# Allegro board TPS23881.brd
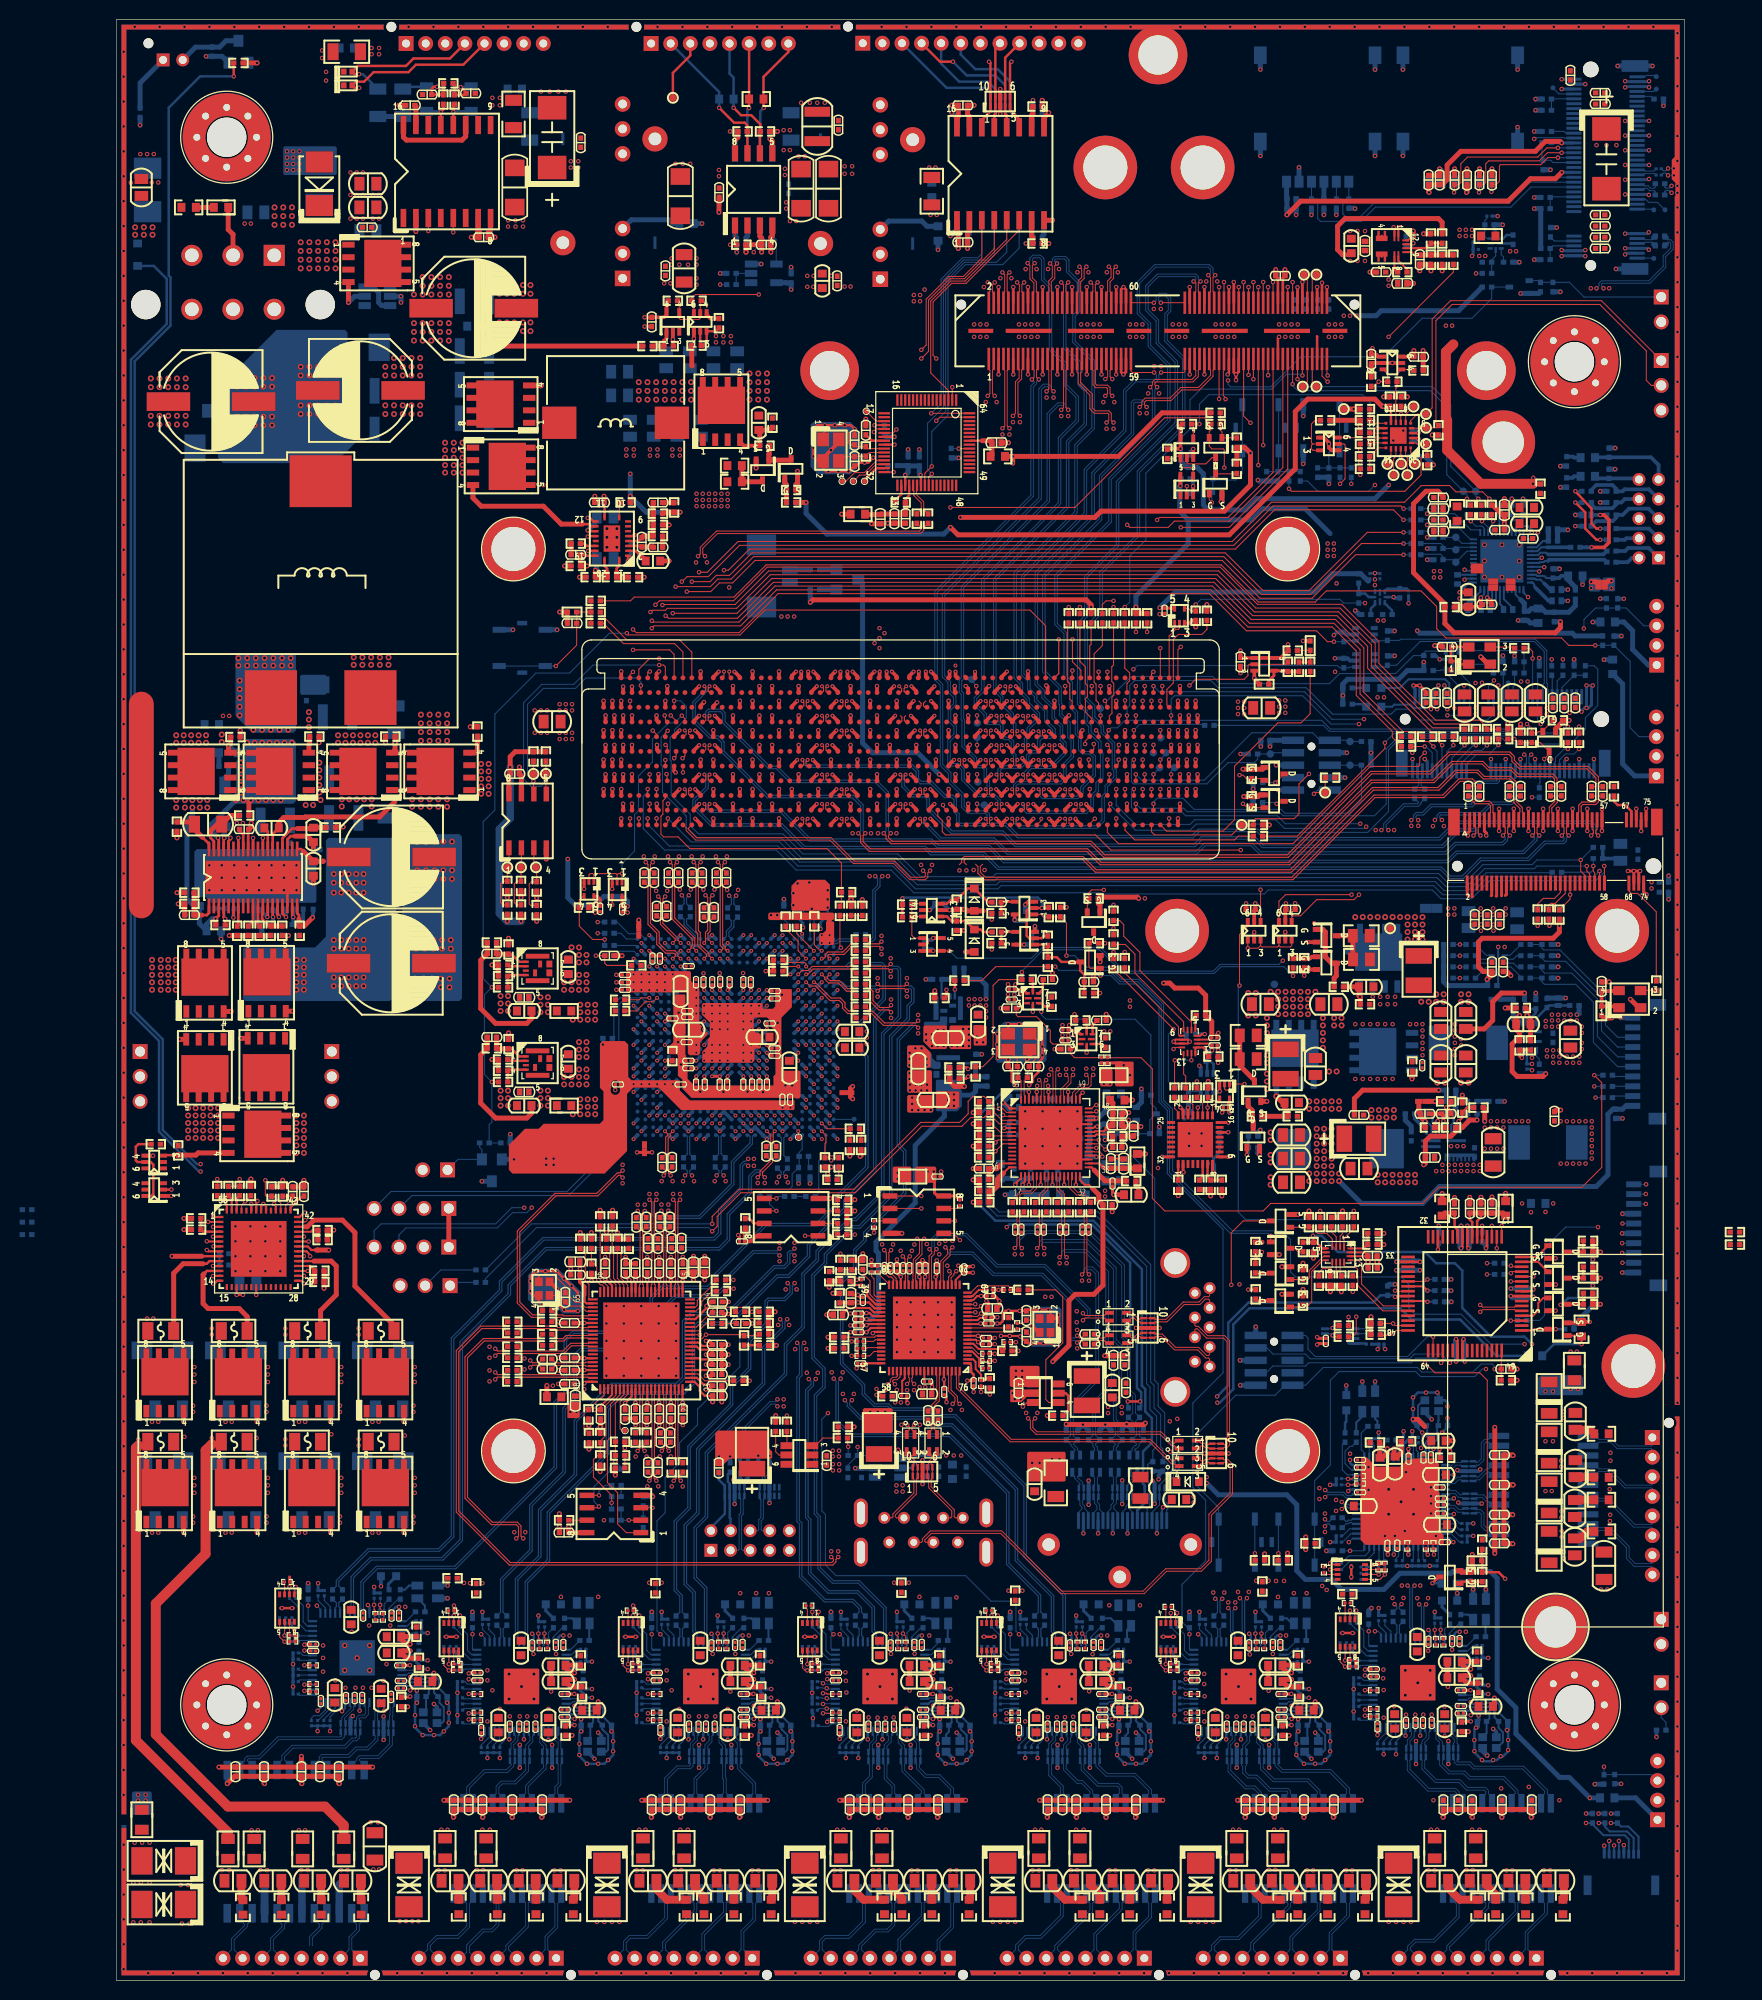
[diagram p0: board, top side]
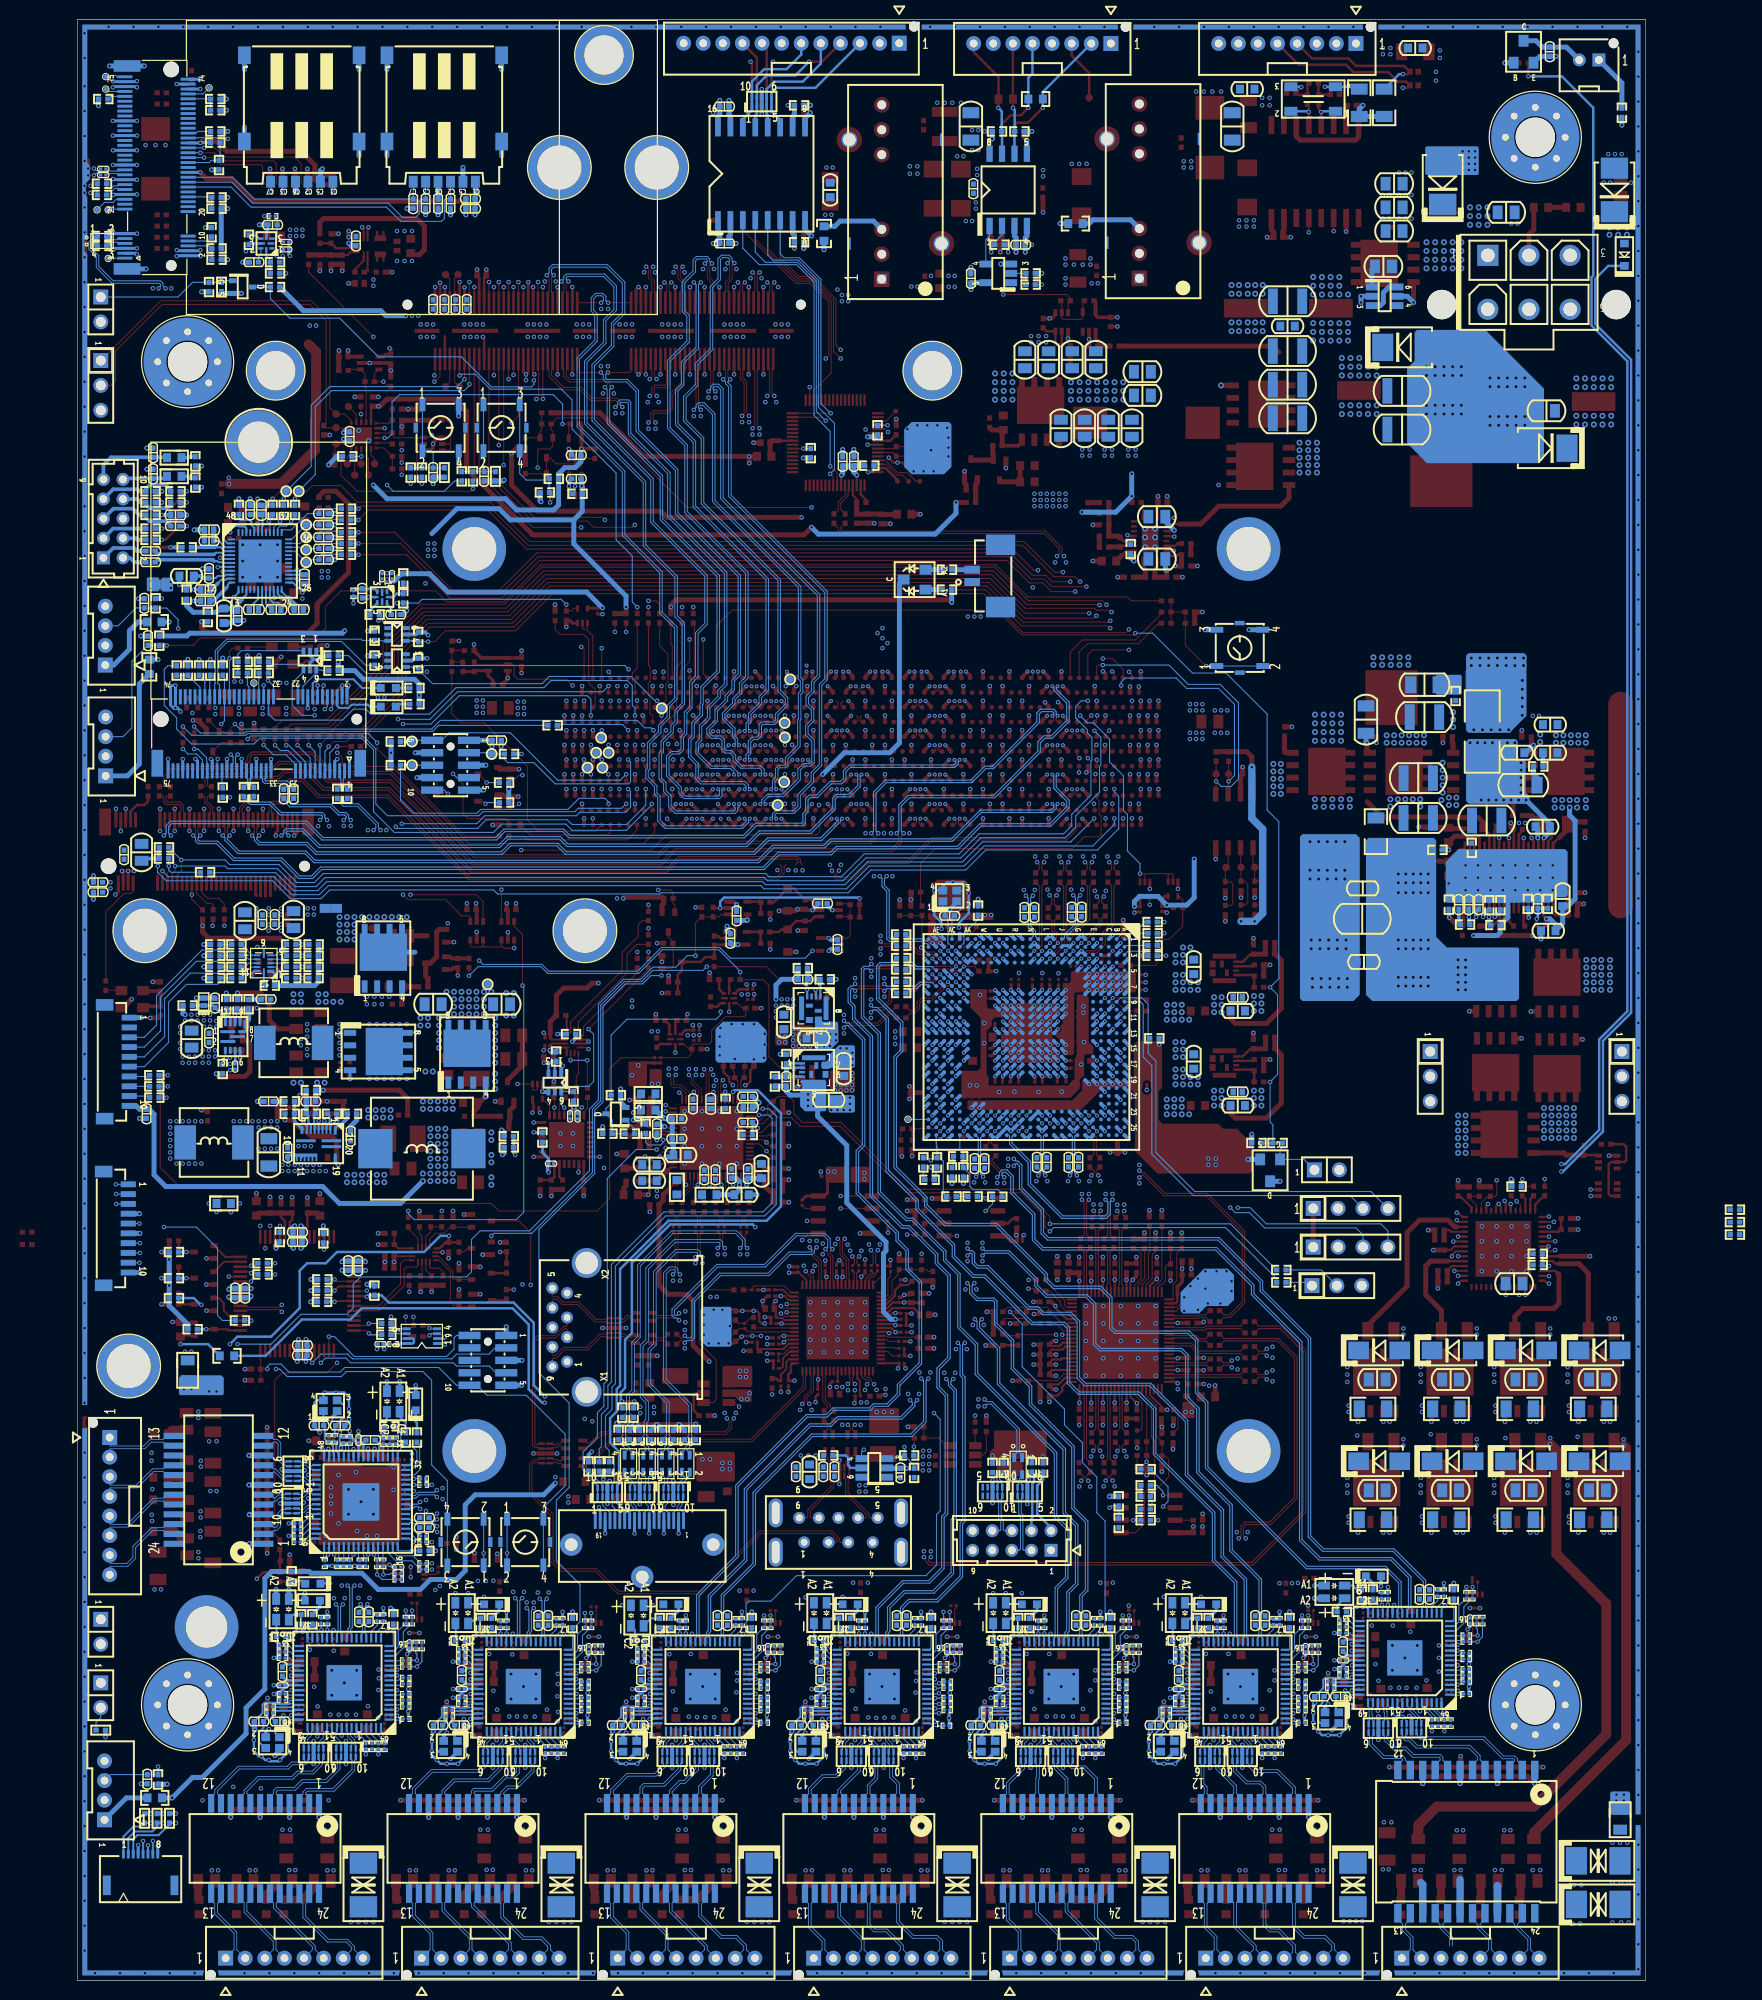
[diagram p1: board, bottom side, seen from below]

Outline 160 x 200 mm; copper layers: TOP, GND1, IN1, IN2, VCC, IN3, GND2, BOTTOM. Coordinates in mm from the lower left corner of the outline.
Outline path: 0,200 160,200 160,0 0,0 0,200

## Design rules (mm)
constraint set DEFAULT: min track width 0.107
net group 422RX: nets 422RX+ 422RX-
net group AUDIO_CP1: nets AUDIO_CPN1 AUDIO_CPP1
net group AUDIO_CP2: nets AUDIO_CPN2 AUDIO_CPP2
net group CAM_TE_RSV: nets CAM_TE_RSV N16109
net group N17978352: nets N17978352 N17978356
net group N17978410: nets N17978406 N17978410
net group N17979269: nets N17979269 N17979281
net group N17981424: nets N17981424 N17981427
net group N17981727: nets N17981727 N17981744
net group N17982049: nets N17982049 N17982065
net group N17982135: nets N17982119 N17982135
net group N17983399: nets N17983399 N17983402
net group N17983405: nets N17983405 N17983408
net group N17983600: nets N17983588 N17983600
net group N17983616: nets N17983612 N17983616
net group N17983708: nets N17983696 N17983708
net group N17983724: nets N17983720 N17983724
net group N17983816: nets N17983804 N17983816
net group N17983832: nets N17983828 N17983832
net group N17985522: nets N17985522 N17985526
net group N17985638: nets N17985638 N17985642
net group N17985774: nets N17985774 N17985778
net group N17985910: nets N17985910 N17985914
net group N17986046: nets N17986046 N17986050
net group N17986184: nets N17986184 N17986188
net group N17986320: nets N17986320 N17986324
net group N17986454: nets N17986454 N17986458
net group N18237080: nets N18237049 N18237080
net group N18237422: nets N18237399 N18237422
net group N18237490: nets N18237476 N18237490
net group N54184803: nets N54184803 N54186028
net group N54465893: nets N54465881 N54465893
net group SBU2: nets SBU1 SBU2
net group TYPEC0_DP-E: nets TYPEC0_DM-E TYPEC0_DP-E
net group USB2_1N_CON: nets USB2_1N_CON USB2_1P_CON
net group USB2_2N_CON: nets USB2_2N_CON USB2_2P_CON
net group USB2_DWN_DM1: nets USB2_DWN_DM1 USB2_DWN_DP1
net group USB2_DWN_DM2: nets USB2_DWN_DM2 USB2_DWN_DP2
net group USB2_DWN_DM3: nets USB2_DWN_DM3 USB2_DWN_DP3
net group USB2_DWN_DP4: nets USB2_DWN_DM4 USB2_DWN_DP4
net group USB3_RXN1_CON: nets USB3_RXN1_CON USB3_RXP1_CON
net group USB3_RXP2_CON: nets USB3_RXN2_CON USB3_RXP2_CON
net group USB3_TXN1_CON: nets USB3_TXN1_CON USB3_TXP1_CON
net group USB3_TXP2_CON: nets USB3_TXN2_CON USB3_TXP2_CON
net group AC97-50OHM: nets I2S1_DIN I2S1_DIN_CDC I2S1_DOUT I2S1_DOUT_CDC I2S1_FS I2S1_FS_CDC I2S1_SCLK I2S1_SCLK_CDC
net group CLK-85OHM: nets 12DPE_CLKN0 12DPE_CLKP0 DPE_CLKN0 DPE_CLKN1 DPE_CLKN2 DPE_CLKP0 DPE_CLKP1 DPE_CLKP2 LAN_CLKN1 LAN_CLKN2 LAN_CLKN3 LAN_CLKN4 LAN_CLKN5 LAN_CLKN6 LAN_CLKN7 LAN_CLKN8 LAN_CLKP1 LAN_CLKP2 LAN_CLKP3 LAN_CLKP4 LAN_CLKP5 LAN_CLKP6 LAN_CLKP7 LAN_CLKP8 N54369784 N54371660 PCIE4_CLK_N PCIE4_CLK_P PCIE5_CLK_N PCIE5_CLK_P UPE_CLKN UPE_CLKP UPHY0_SF_PCIE1_CLK_N UPHY0_SF_PCIE1_CLK_P
net group CLK-OTHER-50OHM: nets 06UPE_CLKREQN 12DPE_CLKREQN0 12DPE_CLKREQN1 12DPE_CLKREQN2 12DPE_CLKREQN3 12DPE_CLKREQN4 12DPE_CLKREQN5 AUD_MCLK01_CDC CLK-ISP0 CLK-ISP0# CLKREQ_M2_KEY_B_N DPE_CLKREQN0 DPE_CLKREQN1 DPE_CLKREQN2 DPE_CLKREQN3 M.2_WIFI_SUS_CLK MCLK01_AUDIO_MCLK MCLK02_CAM0_MCLK MCLK02_MCLK MCLK03_CAM1_MCLK MCLK03_MCLK MCLK04_CAM2_MCLK MCLK04_MCLK NC_SI1_CLK NCSI4_CLKIN P0_TOD_CLK_IN_3V3 P1_TOD_CLK_IN_3V3 PCIE1_CLKREQ_N PCIE4_CLKREQ_N PCIE5_CLKREQ_N SW2CLK UFS0_REF_CLK UPE_CLKREQN
net group CSI-90OHM: nets CSI_0_CLK_N CSI_0_CLK_P CSI_0_D0_N CSI_0_D0_P CSI_0_D1_N CSI_0_D1_P CSI_1_CLK_N CSI_1_CLK_P CSI_1_D0_N CSI_1_D0_P CSI_1_D1_N CSI_1_D1_P CSI_2_CLK_N CSI_2_CLK_P CSI_2_D0_N CSI_2_D0_P CSI_2_D1_N CSI_2_D1_P CSI_3_CLK_N CSI_3_CLK_P CSI_3_D0_N CSI_3_D0_P CSI_3_D1_N CSI_3_D1_P CSI_4_CLK_N CSI_4_CLK_P CSI_4_D0_N CSI_4_D0_P CSI_4_D1_N CSI_4_D1_P CSI_5_CLK_N CSI_5_CLK_P CSI_5_D0_N CSI_5_D0_P CSI_5_D1_N CSI_5_D1_P CSI_6_CLK_N CSI_6_CLK_P CSI_6_D0_N CSI_6_D0_P CSI_6_D1_N CSI_6_D1_P CSI_7_CLK_N CSI_7_CLK_P CSI_7_D0_N CSI_7_D0_P CSI_7_D1_N CSI_7_D1_P
net group EMMC-50OHM: nets N18237134 N18237158 N18237182 N18237217 N18237240 N18237264 SDMMC1_CLK SDMMC1_CMD SDMMC1_D0 SDMMC1_D1 SDMMC1_D2 SDMMC1_D3
net group HDMI-100OHM: nets E_TX0N_A E_TX0N_R_A E_TX0P_A E_TX0P_R_A E_TX1N_A E_TX1N_R_A E_TX1P_A E_TX1P_R_A E_TX2N_A E_TX2N_R_A E_TX2P_A E_TX2P_R_A E_TXCN_A E_TXCN_R_A E_TXCP_A E_TXCP_R_A HDMI_DP0_TX0_N HDMI_DP0_TX0_P HDMI_DP0_TX1_N HDMI_DP0_TX1_P HDMI_DP0_TX2_N HDMI_DP0_TX2_P HDMI_DP0_TX3_N HDMI_DP0_TX3_P TX0N_A TX0N_A-E TX0P_A TX0P_A-E TX1N_A TX1N_A-E TX1P_A TX1P_A-E TX2N_A TX2N_A-E TX2P_A TX2P_A-E TXCN_A TXCN_A-E TXCP_A TXCP_A-E
net group LAN-100OHM: nets LAN1_MDI0+ LAN1_MDI0+_T LAN1_MDI0- LAN1_MDI0-_T LAN1_MDI1+ LAN1_MDI1+_T LAN1_MDI1- LAN1_MDI1-_T LAN1_MDI2+ LAN1_MDI2+_T LAN1_MDI2- LAN1_MDI2-_T LAN1_MDI3+ LAN1_MDI3+_T LAN1_MDI3- LAN1_MDI3-_T LAN2_MDI0+ LAN2_MDI0+_T LAN2_MDI0- LAN2_MDI0-_T LAN2_MDI1+ LAN2_MDI1+_T LAN2_MDI1- LAN2_MDI1-_T LAN2_MDI2+ LAN2_MDI2+_T LAN2_MDI2- LAN2_MDI2-_T LAN2_MDI3+ LAN2_MDI3+_T LAN2_MDI3- LAN2_MDI3-_T LAN3_MDI0+ LAN3_MDI0+_T LAN3_MDI0- LAN3_MDI0-_T LAN3_MDI1+ LAN3_MDI1+_T LAN3_MDI1- LAN3_MDI1-_T LAN3_MDI2+ LAN3_MDI2+_T LAN3_MDI2- LAN3_MDI2-_T LAN3_MDI3+ LAN3_MDI3+_T LAN3_MDI3- LAN3_MDI3-_T LAN4_MDI0+ LAN4_MDI0+_T LAN4_MDI0- LAN4_MDI0-_T LAN4_MDI1+ LAN4_MDI1+_T LAN4_MDI1- LAN4_MDI1-_T LAN4_MDI2+ LAN4_MDI2+_T LAN4_MDI2- LAN4_MDI2-_T LAN4_MDI3+ LAN4_MDI3+_T LAN4_MDI3- LAN4_MDI3-_T LAN5_MDI0+ LAN5_MDI0+_T LAN5_MDI0- LAN5_MDI0-_T LAN5_MDI1+ LAN5_MDI1+_T LAN5_MDI1- LAN5_MDI1-_T LAN5_MDI2+ LAN5_MDI2+_T LAN5_MDI2- LAN5_MDI2-_T LAN5_MDI3+ LAN5_MDI3+_T LAN5_MDI3- LAN5_MDI3-_T LAN6_MDI0+ LAN6_MDI0+_T LAN6_MDI0- LAN6_MDI0-_T LAN6_MDI1+ LAN6_MDI1+_T LAN6_MDI1- LAN6_MDI1-_T LAN6_MDI2+ LAN6_MDI2+_T LAN6_MDI2- LAN6_MDI2-_T LAN6_MDI3+ LAN6_MDI3+_T LAN6_MDI3- LAN6_MDI3-_T LAN7_MDI0+ LAN7_MDI0+_T LAN7_MDI0- LAN7_MDI0-_T LAN7_MDI1+ LAN7_MDI1+_T LAN7_MDI1- LAN7_MDI1-_T LAN7_MDI2+ LAN7_MDI2+_T LAN7_MDI2- LAN7_MDI2-_T LAN7_MDI3+ LAN7_MDI3+_T LAN7_MDI3- LAN7_MDI3-_T LAN8_MDI0+ LAN8_MDI0+_T LAN8_MDI0- LAN8_MDI0-_T LAN8_MDI1+ LAN8_MDI1+_T LAN8_MDI1- LAN8_MDI1-_T LAN8_MDI2+ LAN8_MDI2+_T LAN8_MDI2- LAN8_MDI2-_T LAN8_MDI3+ LAN8_MDI3+_T LAN8_MDI3- LAN8_MDI3-_T
net group NCSI-50OHM: nets NCSI4_ARBIN NCSI4_ARBOUT NCSI4_CRS_DV NCSI4_RXD0 NCSI4_RXD1 NCSI4_TX_EN NCSI4_TXD0 NCSI4_TXD1
net group PCIE4-85OHM: nets UPHY0_RX4_N UPHY0_RX4_P UPHY0_RX5_N UPHY0_RX5_P UPHY0_TX4_N UPHY0_TX4_N_M2M UPHY0_TX4_P UPHY0_TX4_P_M2M UPHY0_TX5_N UPHY0_TX5_N_M2M UPHY0_TX5_P UPHY0_TX5_P_M2M UPHY0_TX6_N_M2M UPHY0_TX6_P_M2M UPHY0_TX7_N_M2M UPHY0_TX7_P_M2M UPHY_RX10_N UPHY_RX10_P UPHY_RX11_N UPHY_RX11_P UPHY_TX10_N UPHY_TX10_P UPHY_TX11_N UPHY_TX11_P
net group PCIE-85OHM: nets 12DPE_RXN0 12DPE_RXN1 12DPE_RXP0 12DPE_RXP1 12DPE_TXN0 12DPE_TXN1 12DPE_TXP0 12DPE_TXP1 DPE_RXN0 DPE_RXN1 DPE_RXN6 DPE_RXP0 DPE_RXP1 DPE_RXP6 DPE_TXN0 DPE_TXN1 DPE_TXN6 DPE_TXP0 DPE_TXP1 DPE_TXP6 N17979323 N17979335 N17979425 N17979437 PCIE_RXN1 PCIE_RXN2 PCIE_RXN3 PCIE_RXN4 PCIE_RXN5 PCIE_RXN6 PCIE_RXN7 PCIE_RXN8 PCIE_RXP1 PCIE_RXP2 PCIE_RXP3 PCIE_RXP4 PCIE_RXP5 PCIE_RXP6 PCIE_RXP7 PCIE_RXP8 PCIE_TXN1 PCIE_TXN2 PCIE_TXN3 PCIE_TXN4 PCIE_TXN5 PCIE_TXN6 PCIE_TXN7 PCIE_TXN8 PCIE_TXP1 PCIE_TXP2 PCIE_TXP3 PCIE_TXP4 PCIE_TXP5 PCIE_TXP6 PCIE_TXP7 PCIE_TXP8 RXPE_UP TXNE_UP TXPE_UP UPE_RXN0 UPE_RXN1 UPE_RXP0 UPE_RXP1 UPE_TXN0 UPE_TXN1 UPE_TXP0 UPE_TXP1 UPHY0_RX2_N UPHY0_RX2_P UPHY0_RX3_N UPHY0_RX3_P UPHY0_TX2_N UPHY0_TX2_P UPHY0_TX3_N UPHY0_TX3_P UPHY1_RX0_N UPHY1_RX0_P UPHY1_RX1_N UPHY1_RX1_P UPHY1_RX2_N UPHY1_RX2_P UPHY1_RX3_N UPHY1_RX3_P UPHY1_TX0_N UPHY1_TX0_P UPHY1_TX1_N UPHY1_TX1_P UPHY1_TX2_N UPHY1_TX2_P UPHY1_TX3_N UPHY1_TX3_P UPHY_RX0_N UPHY_RX0_P UPHY_TX0_N UPHY_TX0_P
net group POWER: nets ISO_+V12S
net group RST-50OHM: nets 06DPE_RSTN 06DPE_RSTN_R 06PERSTN 12DPE_RSTN 1812_RST_N CAM0_RST CAM1_RST DPE_RSTN_R EFM8_RST_MON JTAG_TRST_N M2_5G_PLTRST_N M2_WIFI_PLTRST_N MCU2_RST# PCIE1_RST_N PCIE4_RST_N PCIE5_RST_N PCIE5_RST_N1 PCIE5RST_N PCIE_RST# PLTRST#_TPM POE_RST# SYS_RST_IN_N SYS_RST_IN_N_CON SYS_RST_IN_N_KEY SYS_RST_IN_Q SYSRST#_OOB UFS0_RST_N USBHUB_PLTRST_N
net group RXNE_UP: nets RXNE_UP
net group SMB-50OHM: nets DIO_SCL DIO_SDA DP2_AUX_CH_N_I2C6_DAT DP2_AUX_CH_P_I2C6_CLK EFM8SB10_C2CK EFM8SB10_C2D HMCU_SCL_A HMCU_SDA_A I2C_GP1_CLK I2C_GP1_DAT I2C_GP2_CLK I2C_GP2_CLK_3V3 I2C_GP2_DAT I2C_GP2_DAT_3V3 I2C_GP3_CLK I2C_GP3_DAT I2C_GP9_CLK I2C_GP9_DAT I2C_SCL_CDC I2C_SDA_CDC I2S4_DIN I2S4_DOUT I2S4_FS I2S4_SCLK MCU_SCL_A MCU_SDA_A POE_SCL POE_SDA SPI1_MOSI TX_SCL_A TX_SDA_A
net group SPI-50OHM: nets 3V3_SPI_CLK 3V3_SPI_MISO_IO1 3V3_SPI_MOSI_IO0 06SPI_CS 06SPI_SCK 06SPI_SDIO 06SPI_SDIO1 1812SPI_CS 1812SPI_SCK 1812SPI_SCK_P 1812SPI_SDIO 1812SPI_SDIO1 1812SPI_SDIO_P CAM_SPI_CS0 CAM_SPI_MISO CAM_SPI_MOSI CAM_SPI_SCK P_SPI_CK P_SPI_CZ P_SPI_DI P_SPI_DO P_SPI_HOLD# P_SPI_WP# SPI1_CS0 SPI1_MISO SPI1_SCK TPM_SPI_CS0 TPM_SPI_MISO TPM_SPI_MOSI TPM_SPI_SCK
net group UART-50OHM: nets 06UART_RX 06UART_TX 1812UART_TX 1812UART_TX_P UART0_RX_OOB_3V3 UART0_TX_OOB_3V3 UART1_CTS UART1_RTS UART1_RXD UART1_TXD UART2_CTS UART2_RTS UART2_RX_OOB_3V3 UART2_RXD UART2_RXD_3V3 UART2_TX_OOB_3V3 UART2_TXD UART2_TXD_3V3 UART3_RXD UART3_TXD UART5_CTS UART5_RTS UART5_RXD UART5_TXD UART1812_RX UART1812_TX UART_RXD UART_TXD
net group UIM-50OHM: nets UIM1_CLK UIM1_DATA UIM1_DET UIM1_RESET UIM2_CLK UIM2_DATA UIM2_DET UIM2_RESET
net group USB-90OHM: nets DM DP N60625316 N60625341 N63438290 N63438309 USB2_0_N USB2_0_P USB2_1_N USB2_1_P USB2_2_N USB2_2_P USB2_3_N USB2_3_P USB3_DWN_RXN1 USB3_DWN_RXN2 USB3_DWN_RXP1 USB3_DWN_RXP2 USB3_DWN_TXN1 USB3_DWN_TXN2 USB3_DWN_TXP1 USB3_DWN_TXP2 USB31_RX_DN USB31_RX_DP USB31_TX_DN USB31_TX_DP USB_N0 USB_P0

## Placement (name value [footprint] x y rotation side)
AUDIO1  WF200-10/CI0110P1VD0-NH  [WF200D-5X2P-CI01]  156.34 149.1 270 bottom
AUTOPW1  PH254-2X1  [CONHD2X1]  157.61 30.35 270 bottom
BAT1  WF125-2/85205-02  [WF125S-2P-85205]  68.71 143.26 90 bottom
BUZZ1  WF200-2/B02B-PASK(LF)(SN)  [WF200D-2P-PASK]  4.76 195.89 180 bottom
C1  22U/25V/X5R-C5  [SM0805_C]  116.84 129.79 0 top
C2  22U/25V/X5R-C5  [SM0805_C]  44.45 128.4 180 top
C10  1U/10V/X7R-C2  [SM0402_C]  89.81 106.93 180 top
C18  0.01U/50V/X7R-C2  [SM0402_C]  137.54 76.33 180 bottom
C19  0.01U/50V/X7R-C2  [SM0402_C]  137.03 64.77 180 bottom
C20  0.01U/50V/X7R-C2  [SM0402_C]  131.34 72.9 270 bottom
C21  0.01U/50V/X7R-C2  [SM0402_C]  132.36 72.9 270 bottom
C22  0.01U/50V/X7R-C2  [SM0402_C]  140.34 78.74 90 top
C23  1U/10V/X5R-C2  [SM0402_C]  139.22 78.74 90 top
C24  1U/10V/X5R-C2  [SM0402_C]  141.76 62.36 0 top
C25  1U/10V/X5R-C2  [SM0402_C]  136.53 78.74 90 top
C27  2.2U/25V/X5R-C2  [SM0402_CM]  141.22 149.99 90 bottom
C30  2.2U/25V/X5R-C2  [SM0402_CM]  141.6 149.99 90 top
C34  10U/10V/X5R-C3  [SM0603_C]  143.89 148.59 180 top
C35  10U/10V/X5R-C3  [SM0603_C]  143.89 150.24 180 top
C38  10U/10V/X5R-C3  [SM0603_C]  145.03 139.19 270 bottom
C40  2.2U/25V/X5R-C2  [SM0402_CM]  146.56 147.96 0 bottom
C42  10U/10V/X5R-C3  [SM0603_C]  137.92 140.84 90 top
C43  2.2U/25V/X5R-C2  [SM0402_CM]  139.7 139.83 180 bottom
C44  1U/16V/X5R-C2  [SM0402_C]  149.99 148.34 180 bottom
C45  2.2U/25V/X5R-C2  [SM0402_CM]  141.99 139.83 0 bottom
C46  2.2U/25V/X5R-C2  [SM0402_CM]  137.41 139.83 180 bottom
C47  2.2U/25V/X5R-C2  [SM0402_CM]  136.83 142.9 270 bottom
C54  10U/10V/X5R-C3  [SM0603_C]  148.84 143.26 0 bottom
C57  12P-C2  [SM0402_C]  92.84 67.82 90 top
C58  12P-C2  [SM0402_C]  92.84 65.66 270 top
C59  10U/6.3V/X5R-C2  [SM0402_CM]  74.93 69.6 90 top
C60  @1U/50V/X5R-C2  [SM0402_C]  76.15 72.97 90 top
C61  10U/6.3V/X5R-C2  [SM0402_CM]  82.7 59.82 0 top
C62  10U/6.3V/X5R-C2  [SM0402_CM]  73.61 67.89 180 top
C63  1U/16V/X5R-C2  [SM0402_C]  92.02 60.4 270 top
C64  1U/16V/X5R-C2  [SM0402_C]  76.02 51.77 90 bottom
C65  22U/10V/X5R-C3  [SM0603_C]  101.6 60.2 270 top
C66  470P-C2  [SM0402_C]  101.73 63.25 90 top
C67  22U/10V/X5R-C3  [SM0603_C]  85.29 51.88 90 bottom
C68  470P-C2  [SM0402_C]  83.9 51.89 90 bottom
C69  1U/10V/X5R-C2  [SM0402_C]  79.38 149.1 90 top
C70  1U/10V/X5R-C2  [SM0402_C]  76.45 158.12 90 top
C71  10U/6.3V/X5R-C2  [SM0402_CM]  77.93 149.05 90 top
C72  10P-C2  [SM0402_C]  75.31 154.94 270 top
C73  10P-C2  [SM0402_C]  75.31 157.1 90 top
C74  1000P/3KV-C8  [SM1808_C]  72.64 182.75 90 top
C75  4.7U/16V/X5R-C3  [SM0603_C]  72.01 173.35 270 top
C76  10U/50V/X7R-C10  [SM1210_C]  71.5 189.1 270 top
C77  4.7U/50V/X7R-C6  [SM1206_C]  68.83 189.1 90 bottom
C78  1000P/3KV-C8  [SM1808_C]  69.85 182.75 90 top
C79  1000P-C3  [SM0603_C]  83.19 182.63 90 bottom
C80  1U/16V/X5R-C2  [SM0402_C]  72.47 53.04 90 top
C81  10U/10V/X5R-C5  [SM0805_C]  137.54 130.3 270 top
C82  0.01U/50V/X7R-C2  [SM0402_C]  134.62 130.81 270 top
C83  @10U/10V/X5R-C5  [SM0805_C]  139.95 130.3 270 top
C84  0.01U/50V/X7R-C2  [SM0402_C]  133.6 130.81 270 top
C87  0.01U/50V/X7R-C2  [SM0402_C]  147.7 130.3 270 top
C88  10U/10V/X5R-C5  [SM0805_C]  144.78 130.3 270 top
C89  0.01U/50V/X7R-C2  [SM0402_C]  148.84 130.3 270 top
C90  @10U/10V/X5R-C5  [SM0805_C]  142.37 130.3 270 top
C91  1U/6.3V/X5R-C1  [SM0201_C]  128.91 143.23 90 bottom
C92  1000P-C2  [SM0402_C]  127.51 139.32 180 bottom
C110  4.7P-C2  [SM0402_C]  151.38 192.53 0 top
C111  6.8P-C2  [SM0402_C]  151.38 180.09 180 top
C112  8.2P-C2  [SM0402_C]  148.34 194.31 270 top
C113  10P-C2  [SM0402_C]  151.38 191.39 180 top
C117  33P-C2  [SM0402_C]  123.19 181.23 90 bottom
C118  33P-C2  [SM0402_C]  125.73 181.23 90 bottom
C119  33P-C2  [SM0402_C]  119.89 180.72 180 bottom
C120  33P-C2  [SM0402_C]  124.46 181.23 90 bottom
C121  33P-C2  [SM0402_C]  121.92 181.23 90 bottom
C123  33P-C2  [SM0402_C]  137.79 183.64 270 top
C124  33P-C2  [SM0402_C]  140.34 183.64 270 top
C125  33P-C2  [SM0402_C]  139.06 183.64 270 top
C126  33P-C2  [SM0402_C]  136.53 183.64 270 top
C128  33P-C2  [SM0402_C]  135 183.64 270 top
C129  1U/6.3V/X5R-C1  [SM0201_C]  138.68 176.56 180 bottom
C130  1000P-C2  [SM0402_C]  141.99 175.26 0 bottom
C132  1000P-C2  [SM0402_C]  118.49 153.42 270 bottom
C134  1000P-C2  [SM0402_C]  123.7 153.8 270 bottom
C135  1000P-C2  [SM0402_C]  46.48 138.43 180 top
C136  0.47U/50V/X5R-C2  [SM0402_C]  118.75 173.86 180 top
C137  0.47U/50V/X5R-C2  [SM0402_C]  123.7 170.94 270 bottom
C138  0.47U/50V/X5R-C2  [SM0402_C]  120.27 170.94 270 bottom
C139  0.47U/50V/X5R-C2  [SM0402_C]  121.41 170.94 270 bottom
C140  0.47U/50V/X5R-C2  [SM0402_C]  122.56 170.94 270 bottom
C141  10U/10V/X5R-C2  [SM0402_CM]  131.19 173.1 0 top
C142  10U/10V/X5R-C2  [SM0402_CM]  127.38 176.91 90 top
C143  47U/6.3V/X5R-C3  [SM0603_C]  125.98 176.91 90 top
C155  1000P/3KV-C8  [SM1808_C]  57.53 181.99 90 top
C156  4.7U/50V/X7R-C6  [SM1206_C]  57.91 174.62 270 top
C157  4.7U/50V/X7R-C6  [SM1206_C]  42.16 189.1 90 bottom
C158  1000P/3KV-C8  [SM1808_C]  40.64 182.88 90 top
C159  1000P-C3  [SM0603_C]  40.64 192.91 0 bottom
C160  1000P-C3  [SM0603_C]  23.5 197.1 0 bottom
C162  68P/100V/NPO-C2  [SM0402_C]  31.7 192.35 180 top
C163  4700P-C2  [SM0402_C]  29.97 191.26 0 top
C164  68P/100V/NPO-C2  [SM0402_C]  36.14 192.48 0 top
C166  10U/6.3V/X5R-C3  [SM0603_C]  28.32 35.05 180 top
C167  10U/6.3V/X5R-C3  [SM0603_C]  28.32 33.4 180 top
C168  22U/6.3V/X5R-C3  [SM0603_C]  23.95 37.06 270 top
C169  10U/6.3V/X5R-C3  [SM0603_C]  27 29.01 90 top
C170  10U/6.3V/X5R-C3  [SM0603_C]  31.5 30.48 0 top
C171  0.039U/16V/X7R-C2  [SM0402_C]  30.86 34.04 90 bottom
C172  10U/6.3V/X5R-C3  [SM0603_C]  22.28 29.08 90 top
C173  27P-C2  [SM0402_C]  33.27 28.96 0 bottom
C174  27P-C2  [SM0402_C]  31.11 28.96 180 bottom
C175  10U/6.3V/X5R-C3  [SM0603_C]  45.09 32.13 180 top
C176  10U/6.3V/X5R-C3  [SM0603_C]  45.09 30.48 180 top
C177  22U/6.3V/X5R-C3  [SM0603_C]  41.27 33.91 270 top
C178  10U/6.3V/X5R-C3  [SM0603_C]  44.07 26.04 90 top
C179  10U/6.3V/X5R-C3  [SM0603_C]  48.26 27.56 0 top
C180  0.039U/16V/X7R-C2  [SM0402_C]  47.62 31.11 90 bottom
C181  10U/6.3V/X5R-C3  [SM0603_C]  38.96 26.04 90 top
C182  27P-C2  [SM0402_C]  50.04 26.04 0 bottom
C183  27P-C2  [SM0402_C]  47.88 26.04 180 bottom
C184  10U/6.3V/X5R-C3  [SM0603_C]  63.37 32.13 180 top
C185  10U/6.3V/X5R-C3  [SM0603_C]  63.37 30.48 180 top
C186  22U/6.3V/X5R-C3  [SM0603_C]  59.56 33.91 270 top
C187  10U/6.3V/X5R-C3  [SM0603_C]  62.36 26.04 90 top
C188  10U/6.3V/X5R-C3  [SM0603_C]  66.55 27.56 0 top
C189  0.039U/16V/X7R-C2  [SM0402_C]  65.91 31.11 90 bottom
C190  10U/6.3V/X5R-C3  [SM0603_C]  57.25 26.04 90 top
C191  27P-C2  [SM0402_C]  68.33 26.04 0 bottom
C192  27P-C2  [SM0402_C]  66.17 26.04 180 bottom
C193  10U/6.3V/X5R-C3  [SM0603_C]  81.66 32.13 180 top
C194  10U/6.3V/X5R-C3  [SM0603_C]  81.66 30.48 180 top
C195  22U/6.3V/X5R-C3  [SM0603_C]  77.85 33.91 270 top
C196  10U/6.3V/X5R-C3  [SM0603_C]  80.64 26.04 90 top
C197  10U/6.3V/X5R-C3  [SM0603_C]  84.84 27.56 0 top
C198  0.039U/16V/X7R-C2  [SM0402_C]  84.2 31.11 90 bottom
C199  10U/6.3V/X5R-C3  [SM0603_C]  75.54 26.04 90 top
C200  27P-C2  [SM0402_C]  86.61 26.04 0 bottom
C201  27P-C2  [SM0402_C]  84.45 26.04 180 bottom
C202  10U/6.3V/X5R-C3  [SM0603_C]  99.95 32.13 180 top
C203  10U/6.3V/X5R-C3  [SM0603_C]  99.95 30.48 180 top
C204  22U/6.3V/X5R-C3  [SM0603_C]  96.14 33.91 270 top
C205  10U/6.3V/X5R-C3  [SM0603_C]  98.93 26.04 90 top
C206  0.039U/16V/X7R-C2  [SM0402_C]  102.49 31.11 90 bottom
C207  10U/6.3V/X5R-C3  [SM0603_C]  103.12 27.56 0 top
C208  10U/6.3V/X5R-C3  [SM0603_C]  93.83 26.04 90 top
C209  27P-C2  [SM0402_C]  104.9 26.04 0 bottom
C210  27P-C2  [SM0402_C]  102.74 26.04 180 bottom
C211  10U/6.3V/X5R-C3  [SM0603_C]  118.24 32.13 180 top
C212  10U/6.3V/X5R-C3  [SM0603_C]  118.24 30.48 180 top
C213  22U/6.3V/X5R-C3  [SM0603_C]  114.43 33.91 270 top
C214  10U/6.3V/X5R-C3  [SM0603_C]  117.22 26.04 90 top
C215  10U/6.3V/X5R-C3  [SM0603_C]  121.41 27.56 0 top
C216  0.039U/16V/X7R-C2  [SM0402_C]  120.78 31.11 90 bottom
C217  10U/6.3V/X5R-C3  [SM0603_C]  112.12 26.04 90 top
C218  27P-C2  [SM0402_C]  123.19 26.04 0 bottom
C219  27P-C2  [SM0402_C]  121.03 26.04 180 bottom
C220  10U/6.3V/X5R-C3  [SM0603_C]  136.53 32.51 180 top
C221  10U/6.3V/X5R-C3  [SM0603_C]  136.53 30.86 180 top
C222  22U/6.3V/X5R-C3  [SM0603_C]  132.72 34.29 270 top
C223  10U/6.3V/X5R-C3  [SM0603_C]  135.51 26.42 90 top
C224  10U/6.3V/X5R-C3  [SM0603_C]  139.7 27.94 0 top
C225  0.039U/16V/X7R-C2  [SM0402_C]  139.06 31.5 90 bottom
C226  10U/6.3V/X5R-C3  [SM0603_C]  130.4 26.42 90 top
C227  27P-C2  [SM0402_C]  141.48 26.42 0 bottom
C228  27P-C2  [SM0402_C]  139.32 26.42 180 bottom
C229  10U/6.3V/X5R-C3  [SM0603_C]  128.91 52.58 270 top
C230  10U/6.3V/X5R-C3  [SM0603_C]  130.45 52.69 270 top
C231  22U/6.3V/X5R-C3  [SM0603_C]  126.97 48.39 0 top
C232  10U/6.3V/X5R-C3  [SM0603_C]  134.9 51.56 180 top
C233  10U/6.3V/X5R-C3  [SM0603_C]  134.87 55.04 0 top
C234  0.039U/16V/X7R-C2  [SM0402_C]  130.09 55.12 180 bottom
C235  10U/6.3V/X5R-C3  [SM0603_C]  135 46.48 180 top
C236  27P-C2  [SM0402_C]  133.17 56.59 180 bottom
C237  27P-C2  [SM0402_C]  135.33 56.59 0 bottom
C238  0.022U/250V/X7R-C5  [SM0805_C]  24.08 10.16 180 top
C239  1U/16V/X5R-C2  [SM0402_C]  20.78 21.29 90 top
C240  0.022U/250V/X7R-C5  [SM0805_C]  20.02 10.16 180 top
C241  0.022U/250V/X7R-C5  [SM0805_C]  15.95 10.16 180 top
C242  0.022U/250V/X7R-C5  [SM0805_C]  11.89 10.16 180 top
C243  1U/16V/X5R-C2  [SM0402_C]  40.39 17.91 90 top
C244  0.022U/250V/X7R-C5  [SM0805_C]  45.85 10.16 180 top
C245  0.022U/250V/X7R-C5  [SM0805_C]  41.91 10.16 180 top
C246  0.022U/250V/X7R-C5  [SM0805_C]  37.97 10.16 180 top
C247  0.022U/250V/X7R-C5  [SM0805_C]  34.04 10.16 180 top
C248  1U/16V/X5R-C2  [SM0402_C]  60.58 17.91 90 top
C249  0.022U/250V/X7R-C5  [SM0805_C]  66.04 10.16 180 top
C250  0.022U/250V/X7R-C5  [SM0805_C]  62.1 10.16 180 top
C251  0.022U/250V/X7R-C5  [SM0805_C]  58.17 10.16 180 top
C252  0.022U/250V/X7R-C5  [SM0805_C]  54.23 10.16 180 top
C253  1U/16V/X5R-C2  [SM0402_C]  80.77 17.91 90 top
C254  0.022U/250V/X7R-C5  [SM0805_C]  86.23 10.16 180 top
C255  0.022U/250V/X7R-C5  [SM0805_C]  82.3 10.16 180 top
C256  0.022U/250V/X7R-C5  [SM0805_C]  78.36 10.16 180 top
C257  0.022U/250V/X7R-C5  [SM0805_C]  74.42 10.16 180 top
C258  1U/16V/X5R-C2  [SM0402_C]  100.97 17.91 90 top
C259  0.022U/250V/X7R-C5  [SM0805_C]  106.43 10.16 180 top
C260  0.022U/250V/X7R-C5  [SM0805_C]  102.49 10.16 180 top
C261  0.022U/250V/X7R-C5  [SM0805_C]  98.55 10.16 180 top
C262  0.022U/250V/X7R-C5  [SM0805_C]  94.61 10.16 180 top
C263  1U/16V/X5R-C2  [SM0402_C]  121.16 17.91 90 top
C264  0.022U/250V/X7R-C5  [SM0805_C]  126.62 10.16 180 top
C265  0.022U/250V/X7R-C5  [SM0805_C]  122.68 10.16 180 top
C266  0.022U/250V/X7R-C5  [SM0805_C]  118.75 10.16 180 top
C267  0.022U/250V/X7R-C5  [SM0805_C]  114.81 10.16 180 top
C268  1U/16V/X5R-C2  [SM0402_C]  144.4 17.91 90 top
C269  0.022U/250V/X7R-C5  [SM0805_C]  146.81 10.16 180 top
C270  0.022U/250V/X7R-C5  [SM0805_C]  142.88 10.16 180 top
C271  0.022U/250V/X7R-C5  [SM0805_C]  138.94 10.16 180 top
C272  0.022U/250V/X7R-C5  [SM0805_C]  135 10.16 180 top
C273  1U/16V/X5R-C2  [SM0402_C]  141.1 50.55 180 top
C274  0.022U/250V/X7R-C5  [SM0805_C]  148.84 57.02 90 top
C275  0.022U/250V/X7R-C5  [SM0805_C]  148.84 52.2 90 top
C276  0.022U/250V/X7R-C5  [SM0805_C]  148.79 48.13 270 top
C277  0.022U/250V/X7R-C5  [SM0805_C]  148.79 44.22 270 top
C279  0.1U/100V/X7R-C5  [SM0805_C]  13.41 71.07 0 bottom
C280  0.1U/100V/X7R-C5  [SM0805_C]  4.9 49.99 180 bottom
C281  0.1U/100V/X7R-C5  [SM0805_C]  12.4 49.99 180 bottom
C282  0.1U/100V/X7R-C5  [SM0805_C]  4.9 61.29 180 bottom
C283  0.1U/100V/X7R-C5  [SM0805_C]  12.4 61.29 180 bottom
C284  0.1U/100V/X7R-C5  [SM0805_C]  19.89 49.99 180 bottom
C285  0.1U/100V/X7R-C5  [SM0805_C]  19.89 61.29 180 bottom
C286  0.1U/100V/X7R-C5  [SM0805_C]  27.38 49.99 180 bottom
C287  0.1U/100V/X7R-C5  [SM0805_C]  27.38 61.29 180 bottom
C288  1U/10V/X5R-C2  [SM0402_C]  103.78 86.61 90 top
C289  1000P-C2  [SM0402_C]  102.11 84.96 0 top
C290  4.7U/16V/X5R-C3  [SM0603_C]  103.53 80.14 180 top
C291  1U/10V/X5R-C2  [SM0402_C]  101.12 79.12 180 top
C292  22U/6.3V/X5R-C3  [SM0603_C]  108.41 49.05 180 top
C293  20P-C2  [SM0402_C]  93.6 93.22 0 top
C294  1000P-C3  [SM0603_C]  93.68 50.62 270 top
C295  20P-C2  [SM0402_C]  91.44 93.22 180 top
C296  1U/10V/X5R-C2  [SM0402_C]  91.59 87.5 0 bottom
C297  1U/10V/X5R-C2  [SM0402_C]  88.52 82.8 0 top
C298  10U/6.3V/X5R-C2  [SM0402_CM]  91.59 89.03 0 bottom
C299  1U/10V/X5R-C2  [SM0402_C]  91.59 90.17 0 bottom
C300  1U/10V/X5R-C2  [SM0402_C]  100.86 86.87 270 bottom
C301  10U/6.3V/X5R-C2  [SM0402_CM]  95.38 89.41 270 bottom
C302  1U/10V/X5R-C2  [SM0402_C]  97.18 89.41 270 bottom
C303  22U/6.3V/X5R-C3  [SM0603_C]  101.63 83.21 0 bottom
C304  22U/6.3V/X5R-C3  [SM0603_C]  101.63 81.56 0 bottom
C305  1U/10V/X5R-C2  [SM0402_C]  94.89 82.17 90 bottom
C306  1U/10V/X5R-C2  [SM0402_C]  96.04 82.17 90 bottom
C307  10U/6.3V/X5R-C2  [SM0402_CM]  102.77 83.31 90 top
C308  1U/10V/X5R-C2  [SM0402_C]  101.45 83.31 90 top
C309  10U/6.3V/X5R-C2  [SM0402_CM]  102.11 87.25 0 top
C310  1U/10V/X5R-C2  [SM0402_C]  102.13 88.39 0 top
C311  22U/6.3V/X5R-C3  [SM0603_C]  92.23 80.14 180 bottom
C312  1U/10V/X5R-C2  [SM0402_C]  93.24 82.3 90 bottom
C313  22U/6.3V/X5R-C3  [SM0603_C]  90.2 82.55 90 bottom
C314  22U/6.3V/X5R-C3  [SM0603_C]  98.45 84.2 180 bottom
C315  1U/10V/X5R-C2  [SM0402_C]  98.83 87.88 180 bottom
C316  1U/10V/X5R-C2  [SM0402_C]  98.83 85.85 180 bottom
C317  1U/10V/X5R-C2  [SM0402_C]  91.59 82.3 90 bottom
C318  @1U/16V/X5R-C2  [SM0402_C]  50.29 104.52 0 top
C319  10P-C2  [SM0402_C]  70.99 108.58 180 bottom
C323  22U/6.3V/X5R-C3  [SM0603_C]  65.89 96.22 180 top
C324  22U/6.3V/X5R-C3  [SM0603_C]  68.66 93.07 270 top
C326  22U/6.3V/X5R-C3  [SM0603_C]  58.39 96.98 180 top
C327  22U/6.3V/X5R-C3  [SM0603_C]  75.06 96.77 0 top
C329  22U/6.3V/X5R-C3  [SM0603_C]  57.56 100.89 270 top
C330  22U/6.3V/X5R-C3  [SM0603_C]  75.06 95.12 0 top
C332  1U/6.3V/X5R-C1  [SM0201_C]  64.85 91.38 270 top
C333  1U/6.3V/X5R-C1  [SM0201_C]  60.02 91.38 270 top
C335  1U/6.3V/X5R-C1  [SM0201_C]  63.96 101.82 90 top
C336  1U/6.3V/X5R-C1  [SM0201_C]  65.61 91.38 270 top
C337  1U/6.3V/X5R-C1  [SM0201_C]  59.13 101.82 90 top
C338  1U/6.3V/X5R-C1  [SM0201_C]  59.89 101.82 90 top
C339  1U/6.3V/X5R-C1  [SM0201_C]  67.14 95.07 0 top
C340  1U/6.3V/X5R-C1  [SM0201_C]  58.36 93.8 180 top
C341  1U/6.3V/X5R-C1  [SM0201_C]  55.45 104.23 90 top
C342  1U/6.3V/X5R-C1  [SM0201_C]  66.64 97.61 0 top
C343  1U/6.3V/X5R-C1  [SM0201_C]  66.37 91.38 270 top
C344  1U/6.3V/X5R-C1  [SM0201_C]  54.69 104.23 90 top
C345  1U/6.3V/X5R-C1  [SM0201_C]  51.88 101.8 180 top
C346  1U/6.3V/X5R-C1  [SM0201_C]  58.36 93.04 180 top
C347  1U/6.3V/X5R-C1  [SM0201_C]  58.38 103.45 0 top
C348  1U/6.3V/X5R-C1  [SM0201_C]  51.88 101.04 180 top
C349  1U/6.3V/X5R-C1  [SM0201_C]  61.59 101.85 90 top
C350  1U/6.3V/X5R-C1  [SM0201_C]  63.96 91.38 270 top
C351  1U/6.3V/X5R-C1  [SM0201_C]  64.72 101.82 90 top
C352  1U/6.3V/X5R-C1  [SM0201_C]  67.14 100.15 0 top
C353  1U/6.3V/X5R-C1  [SM0201_C]  59.13 91.38 270 top
C354  1U/6.3V/X5R-C1  [SM0201_C]  67.14 94.31 0 top
C355  1U/6.3V/X5R-C1  [SM0201_C]  60.78 101.82 90 top
C356  1U/6.3V/X5R-C1  [SM0201_C]  62.56 101.82 90 top
C357  1U/6.3V/X5R-C1  [SM0201_C]  56.73 98.12 0 top
C358  1U/6.3V/X5R-C1  [SM0201_C]  67.14 100.91 0 top
C359  1U/6.3V/X5R-C1  [SM0201_C]  62.31 91.38 270 top
C360  1U/6.3V/X5R-C1  [SM0201_C]  51.88 102.57 180 top
C361  1U/6.3V/X5R-C1  [SM0201_C]  58.23 98.88 180 top
C362  1U/6.3V/X5R-C1  [SM0201_C]  58.18 95.71 180 top
C363  1U/6.3V/X5R-C1  [SM0201_C]  58.23 98.25 180 top
C364  1U/6.3V/X5R-C1  [SM0201_C]  61.54 91.38 270 top
C369  @1U/10V/X5R-C2  [SM0402_C]  61.29 68.15 0 top
C370  @1U/10V/X5R-C2  [SM0402_C]  63.7 67.01 0 top
C371  10P-C2  [SM0402_C]  45.8 69.67 90 top
C374  2.2U/25V/X5R-C2  [SM0402_CM]  41.61 100.28 180 top
C375  2.2U/25V/X5R-C2  [SM0402_CM]  46.81 59.13 270 top
C376  2.2U/25V/X5R-C2  [SM0402_CM]  41.61 90.63 180 top
C377  2.2U/25V/X5R-C2  [SM0402_CM]  60.02 72.72 90 top
C378  10U/10V/X5R-C3  [SM0603_C]  46.1 93.73 90 top
C379  10U/10V/X5R-C3  [SM0603_C]  46.1 93.73 90 bottom
C380  470P-C2  [SM0402_C]  38.3 96.22 0 top
C381  22U/10V/X5R-C3  [SM0603_C]  41.61 89.23 180 top
C382  22U/10V/X5R-C3  [SM0603_C]  41.61 89.23 180 bottom
C383  10U/10V/X5R-C3  [SM0603_C]  46.1 103.38 90 top
C384  10U/10V/X5R-C3  [SM0603_C]  46.1 103.38 90 bottom
C385  470P-C2  [SM0402_C]  38.3 104.72 0 top
C386  22U/10V/X5R-C3  [SM0603_C]  41.61 98.88 180 top
C387  22U/10V/X5R-C3  [SM0603_C]  41.61 98.88 180 bottom
C388  10U/100V/X7R-C10  [SM1210_C30]  36.53 171.27 0 bottom
C389  0.1U/100V/X7R-C3  [SM0603_C]  36.53 168.73 180 bottom
C390  0.022U/250V/X7R-C5  [SM0805_C]  2.54 182.88 90 top
C391  0.022U/250V/X7R-C5  [SM0805_C]  14.22 180.34 180 bottom
C392  0.1U/100V/X7R-C5  [SM0805_C]  26.75 174.83 0 bottom
C393  0.022U/250V/X7R-C5  [SM0805_C]  10.11 160.1 0 bottom
C394  4.7U/16V/X7R-C3  [SM0603_C]  65.53 158.88 270 top
C395  1U/16V/X5R-C2  [SM0402_C]  132.11 86.11 270 bottom
C396  1U/16V/X5R-C2  [SM0402_C]  146.71 88.14 90 top
C397  1U/16V/X5R-C2  [SM0402_C]  138.56 84.45 270 bottom
C398  10U/25V/X5R-C6  [SM1206_C]  140.46 84.45 270 top
C399  10U/25V/X5R-C6  [SM1206_C]  140.46 84.45 270 bottom
C400  27P-C2  [SM0402_C]  136.17 89.66 180 bottom
C401  22U/10V/X5R-C5  [SM0805_C]  119.89 86.23 180 top
C402  22U/10V/X5R-C5  [SM0805_C]  126.77 82.8 0 top
C403  22U/10V/X5R-C5  [SM0805_C]  119.89 81.41 180 top
C404  22U/10V/X5R-C5  [SM0805_C]  119.89 83.82 180 top
C405  2200P-C2  [SM0402_C]  133.5 88.39 180 top
C406  2.2U/25V/X5R-C2  [SM0402_CM]  134.01 83.95 0 top
C407  4.7U/16V/X7R-C3  [SM0603_C]  119.91 89.53 180 top
C409  22U/16V/X6S-C5  [SM0805_C]  148.34 96.01 270 top
C410  22U/16V/X6S-C5  [SM0805_C]  148.34 96.01 270 bottom
C412  22U/16V/X6S-C5  [SM0805_C]  135.13 97.92 90 top
C413  22U/16V/X6S-C5  [SM0805_C]  137.67 97.92 90 top
C414  22U/16V/X6S-C5  [SM0805_C]  137.67 93.47 270 top
C415  22U/16V/X6S-C5  [SM0805_C]  135.13 93.47 270 top
C417  @0.1U/50V/X7R-C2  [SM0402_C]  145.95 99.69 90 bottom
C418  1U/25V/X7R-C3  [SM0603_C]  143.54 97.54 0 top
C419  4.7U/16V/X7R-C3  [SM0603_C]  127.51 101.35 180 top
C420  10U/10V/X5R-C3  [SM0603_C]  84.86 96.11 180 bottom
C421  10U/10V/X5R-C3  [SM0603_C]  84.86 96.11 180 top
C422  10U/10V/X5R-C3  [SM0603_C]  81.81 92.99 90 bottom
C423  10U/10V/X5R-C3  [SM0603_C]  81.81 92.99 90 top
C424  470P-C2  [SM0402_C]  85.98 102.11 180 bottom
C425  22U/10V/X5R-C3  [SM0603_C]  87.91 97.76 270 top
C426  22U/10V/X5R-C3  [SM0603_C]  87.91 97.76 270 bottom
C427  470P-C2  [SM0402_C]  87.66 91.69 90 bottom
C428  22U/10V/X5R-C3  [SM0603_C]  83.34 89.81 180 top
C429  22U/10V/X5R-C3  [SM0603_C]  83.34 89.81 180 bottom
C430  1U/6.3V/X5R-C1  [SM0201_C]  91.34 100.05 180 top
C431  1U/6.3V/X5R-C1  [SM0201_C]  96.82 95.89 180 top
C432  1000P-C2  [SM0402_C]  100.51 97.92 0 top
C434  1000P-C2  [SM0402_C]  95.02 102.08 0 top
C436  0.1U/100V/X7R-C5  [SM0805_C]  49.86 144.98 0 bottom
C437  2.2U/100V/X7R-C10  [SM1210_C]  24.84 162.13 180 bottom
C438  2.2U/100V/X7R-C10  [SM1210_C]  36.53 166.19 0 bottom
C439  2.2U/100V/X7R-C10  [SM1210_C]  36.53 162.76 0 bottom
C440  1800P-C2  [SM0402_C]  55.24 150.75 180 top
C441  4700P-C2  [SM0402_C]  55.24 146.18 0 top
C442  2.2U/100V/X7R-C10  [SM1210_C]  24.84 158.19 180 bottom
C443  2.2U/100V/X7R-C10  [SM1210_C]  36.53 159.33 0 bottom
C444  0.047U/50V/X7R-C3  [SM0603_C]  54.74 144.78 0 top
C446  82P-C2  [SM0402_C]  53.59 146.69 90 top
C447  22U/16V/X6S-C5  [SM0805_C]  51.33 161.67 180 bottom
C448  22U/16V/X6S-C5  [SM0805_C]  59.64 158.32 270 bottom
C449  22U/16V/X6S-C5  [SM0805_C]  58.5 165.3 90 bottom
C450  22U/16V/X6S-C5  [SM0805_C]  52.4 158.32 270 bottom
C451  22U/16V/X6S-C5  [SM0805_C]  56.08 165.3 90 bottom
C452  22U/16V/X6S-C5  [SM0805_C]  63.32 165.3 90 bottom
C453  22U/16V/X6S-C5  [SM0805_C]  60.91 165.3 90 bottom
C454  22U/16V/X6S-C5  [SM0805_C]  57.23 158.32 270 bottom
C455  22U/16V/X6S-C5  [SM0805_C]  54.81 158.32 270 bottom
C456  22U/16V/X6S-C5  [SM0805_C]  51.33 164.08 180 bottom
C457  10P-C2  [SM0402_C]  49.28 150.75 0 top
C458  2.2U/25V/X7R-C5  [SM0805_C]  49.86 149.3 0 bottom
C459  0.1U/100V/X7R-C3  [SM0603_C]  8.46 110.31 270 bottom
C460  0.1U/100V/X7R-C3  [SM0603_C]  20.09 113.41 90 top
C462  0.1U/100V/X7R-C3  [SM0603_C]  9.73 125.22 180 bottom
C463  10U/100V/X7R-C10  [SM1210_C30]  22.56 128.85 180 bottom
C464  10U/100V/X7R-C10  [SM1210_C30]  23.19 122.63 180 bottom
C465  10U/100V/X7R-C10  [SM1210_C30]  23.19 118.57 180 bottom
C466  4.7U/100V/X7R-C10  [SM1210_C30]  28.91 108.28 180 bottom
C467  1500P/100V/NPO-C6  [SM1206_C]  28.52 128.6 90 bottom
C468  47U/16V/X5R-C10  [SM1210_C]  16.21 118.31 180 bottom
C469  0.1U/100V/X7R-C3  [SM0603_C]  9.73 128.09 180 bottom
C470  180P-C6  [SM1206_C]  9.35 117.93 0 top
C471  1000P-C2  [SM0402_C]  11 109.8 270 bottom
C472  0.1U/100V/X7R-C3  [SM0603_C]  10.49 117.68 0 bottom
C473  0.1U/100V/X7R-C3  [SM0603_C]  15.82 117.55 180 top
C474  680P/630V/NPO-C6  [SM1206_C]  22.56 132.16 0 bottom
C475  68P/100V/NPO-C2  [SM0402_C]  18.03 109.73 270 bottom
C476  0.082U/16V/X7R-C2  [SM0402_C]  19.05 109.73 270 bottom
C477  0.047U/16V/X7R-C2  [SM0402_C]  17.02 109.73 270 bottom
C479  10U/10V/X5R-C5  [SM0805_C]  137.95 108.2 270 bottom
C480  0.01U/50V/X7R-C2  [SM0402_C]  139.85 108.2 270 bottom
C481  10U/10V/X5R-C5  [SM0805_C]  142.9 108.08 270 bottom
C482  0.01U/50V/X7R-C2  [SM0402_C]  139.85 108.2 270 top
C483  0.01U/50V/X7R-C2  [SM0402_C]  138.58 108.2 270 top
C486  10U/10V/X5R-C5  [SM0805_C]  153.44 115.06 90 bottom
C487  0.01U/50V/X7R-C2  [SM0402_C]  157.89 111 0 bottom
C488  0.01U/50V/X7R-C2  [SM0402_C]  155.23 114.82 90 bottom
C499  4.7U/10V/X5R-C2  [SM0402_CM]  89.36 68.53 0 top
C838  100P-C2  [SM0402_C]  152.27 155.83 90 bottom
C839  100P-C2  [SM0402_C]  152.27 153.67 90 bottom
C891  0.1U/10V/X5R-C1  [SM0201_C]  123.39 65.23 270 top
C892  0.1U/10V/X5R-C1  [SM0201_C]  129.06 64.9 180 bottom
C894  1U/10V/X7R-C2  [SM0402_C]  89.79 109.98 180 top
C898  1U/16V/X5R-C2  [SM0402_C]  152.53 145.8 180 bottom
C899  1U/16V/X5R-C2  [SM0402_C]  152.53 144.65 180 bottom
C900  22U/25V/X5R-C5  [SM0805_C]  25.65 183.26 180 bottom
C901  22U/25V/X5R-C5  [SM0805_C]  25.65 180.85 180 top
C902  22U/25V/X5R-C5  [SM0805_C]  25.65 178.44 180 bottom
C903  22U/25V/X5R-C5  [SM0805_C]  25.65 183.26 180 top
C904  22U/25V/X5R-C5  [SM0805_C]  25.65 180.85 180 bottom
C905  22U/25V/X5R-C5  [SM0805_C]  122.33 93.22 270 top
C906  22U/25V/X5R-C5  [SM0805_C]  123.7 99.57 0 bottom
C907  22U/25V/X5R-C5  [SM0805_C]  116.71 99.57 180 bottom
C908  22U/25V/X5R-C5  [SM0805_C]  116.71 99.57 180 top
C909  22U/25V/X5R-C5  [SM0805_C]  123.7 99.57 0 top
C910  10U/6.3V/X5R-C2  [SM0402_CM]  134.87 147.83 180 top
C911  10U/6.3V/X5R-C2  [SM0402_CM]  134.87 150.11 180 top
C912  @22P-C2  [SM0402_C]  134.87 146.05 180 bottom
C913  @22P-C2  [SM0402_C]  134.87 144.91 180 bottom
C914  @22P-C2  [SM0402_C]  134.87 147.19 180 bottom
C915  @22P-C2  [SM0402_C]  134.87 148.46 180 bottom
C916  @22P-C2  [SM0402_C]  134.87 149.61 180 bottom
C917  680P/630V/NPO-C6  [SM1206_C]  12.47 121.92 0 bottom
C918  0.1U/100V/X7R-C3  [SM0603_C]  20.09 116.84 90 top
C919  @0.01U/100V/X7R-C3  [SM0603_C]  13.11 125.22 180 bottom
C920  0.1U/100V/X7R-C3  [SM0603_C]  28.85 111.38 0 bottom
C921  0.1U/100V/X7R-C3  [SM0603_C]  28.73 103.89 0 bottom
C922  0.1U/100V/X7R-C3  [SM0603_C]  9.93 107.06 180 bottom
CA1  0.1U/50V/X7R-C2  [SM0402_C]  86.36 191.26 0 top
CA2  0.1U/50V/X7R-C2  [SM0402_C]  73.66 189.23 90 top
CA3  0.1U/50V/X7R-C2  [SM0402_C]  47.37 187.45 90 top
CA4  0.1U/50V/X7R-C2  [SM0402_C]  133.86 183.64 90 top
CA5  0.1U/50V/X7R-C2  [SM0402_C]  61.49 182.35 270 top
CA6  0.1U/50V/X7R-C2  [SM0402_C]  151.38 178.94 180 top
CA7  0.1U/50V/X7R-C2  [SM0402_C]  25.58 178.82 180 top
CA8  0.1U/50V/X7R-C2  [SM0402_C]  37.47 177.8 0 top
CA9  0.1U/50V/X7R-C2  [SM0402_C]  151.38 177.8 180 top
CA10  0.1U/50V/X7R-C2  [SM0402_C]  86.36 177.29 0 top
CA11  0.1U/50V/X7R-C2  [SM0402_C]  66.29 177.04 0 top
CA12  0.1U/50V/X7R-C2  [SM0402_C]  151.38 176.66 180 top
CA13  0.1U/50V/X7R-C2  [SM0402_C]  132.97 175.51 270 top
CA14  4.7U/10V/X5R-C2  [SM0402_CM]  149.99 149.48 180 bottom
CA15  4.7U/10V/X5R-C2  [SM0402_CM]  146.94 141.86 0 bottom
CA16  4.7U/10V/X5R-C2  [SM0402_CM]  146.94 140.72 0 bottom
CA17  0.1U/50V/X7R-C2  [SM0402_C]  56.01 174.37 270 top
CA18  0.1U/50V/X7R-C2  [SM0402_C]  129.03 174.24 180 top
CA19  0.1U/50V/X7R-C2  [SM0402_C]  73.53 173.35 270 top
CA20  0.1U/10V/X5R-C1  [SM0201_C]  80.9 72.64 270 top
CA21  0.1U/10V/X5R-C1  [SM0201_C]  80.26 72.64 270 top
CA22  0.1U/10V/X5R-C1  [SM0201_C]  83.77 81.99 0 top
CA23  0.1U/10V/X5R-C1  [SM0201_C]  78.99 72.64 270 top
CA24  0.1U/10V/X5R-C1  [SM0201_C]  78.36 72.64 270 top
CA25  0.1U/10V/X5R-C1  [SM0201_C]  87.45 60.91 270 top
CA26  0.1U/10V/X5R-C1  [SM0201_C]  75.69 67.44 180 top
CA27  0.1U/10V/X5R-C1  [SM0201_C]  89.1 69.8 0 top
CA28  0.1U/10V/X5R-C1  [SM0201_C]  76.15 69.42 90 top
CA29  0.1U/10V/X5R-C1  [SM0201_C]  86.49 72.52 90 top
CA30  0.1U/10V/X5R-C1  [SM0201_C]  80.37 59.61 0 top
CA31  0.1U/10V/X5R-C1  [SM0201_C]  88.72 64.9 0 top
CA32  0.1U/10V/X5R-C1  [SM0201_C]  88.98 67.01 0 top
CA33  0.1U/10V/X5R-C1  [SM0201_C]  81.92 72.64 90 top
CA34  0.1U/10V/X5R-C1  [SM0201_C]  79.63 72.64 90 top
CA35  0.1U/10V/X5R-C1  [SM0201_C]  82.55 72.64 90 top
CA36  0.1U/10V/X5R-C1  [SM0201_C]  75.69 66.12 180 top
CA37  0.1U/10V/X5R-C1  [SM0201_C]  75.9 62.94 180 top
CA38  0.1U/10V/X5R-C1  [SM0201_C]  83.69 72.64 90 top
CA39  0.1U/10V/X5R-C1  [SM0201_C]  88.72 65.53 0 top
CA40  0.1U/10V/X5R-C1  [SM0201_C]  84.45 60.02 270 top
CA41  0.1U/10V/X5R-C1  [SM0201_C]  82.7 61.09 0 top
CA42  0.1U/10V/X5R-C1  [SM0201_C]  88.98 67.64 0 top
CA43  0.1U/10V/X5R-C1  [SM0201_C]  75.69 66.8 180 top
CA44  0.1U/10V/X5R-C1  [SM0201_C]  75.69 68.02 180 top
CA45  0.1U/50V/X7R-C2  [SM0402_C]  54.61 169.16 270 top
CA46  0.1U/50V/X7R-C2  [SM0402_C]  132.84 165.61 0 top
CA47  0.1U/50V/X7R-C2  [SM0402_C]  128.02 165.35 90 top
CA48  0.1U/50V/X7R-C2  [SM0402_C]  134.87 151.26 180 top
CA49  0.1U/50V/X7R-C2  [SM0402_C]  80.52 149.1 90 top
CA50  0.1U/50V/X7R-C2  [SM0402_C]  134.87 148.97 180 top
CA51  0.1U/50V/X7R-C2  [SM0402_C]  141.12 147.96 180 top
CA52  0.1U/50V/X7R-C2  [SM0402_C]  144.02 147.07 180 top
CA53  0.1U/50V/X7R-C2  [SM0402_C]  46.86 145.41 0 top
CA54  0.1U/50V/X7R-C2  [SM0402_C]  139.83 140.34 0 top
CA55  0.1U/50V/X7R-C2  [SM0402_C]  135.76 136.02 180 top
CA56  0.1U/50V/X7R-C2  [SM0402_C]  114.68 134.49 270 top
CA57  0.1U/50V/X7R-C2  [SM0402_C]  135.76 130.81 270 top
CA58  0.1U/50V/X7R-C2  [SM0402_C]  146.56 130.3 270 top
CA59  0.1U/50V/X7R-C2  [SM0402_C]  40.64 123.06 0 top
CA60  0.1U/50V/X7R-C2  [SM0402_C]  13.03 117.42 0 top
CA61  0.1U/50V/X7R-C2  [SM0402_C]  99.21 101.85 0 top
CA62  0.1U/50V/X7R-C2  [SM0402_C]  115.72 109.22 0 top
CA63  0.1U/50V/X7R-C2  [SM0402_C]  119.79 109.22 180 top
CA64  0.1U/50V/X7R-C2  [SM0402_C]  7.44 108.66 180 top
CA65  0.1U/50V/X7R-C2  [SM0402_C]  151.52 101.38 90 top
CA66  0.1U/50V/X7R-C2  [SM0402_C]  135.66 88.39 180 top
CA67  0.1U/50V/X7R-C2  [SM0402_C]  126.77 88.27 0 top
CA68  0.1U/50V/X7R-C2  [SM0402_C]  19.13 80.47 270 top
CA69  0.1U/50V/X7R-C2  [SM0402_C]  138.07 78.74 90 top
CA70  0.1U/50V/X7R-C2  [SM0402_C]  128.14 73.91 0 top
CA71  0.1U/50V/X7R-C2  [SM0402_C]  128.17 72.64 0 top
CA72  0.1U/50V/X7R-C2  [SM0402_C]  49.86 72.64 90 top
CA73  0.1U/50V/X7R-C2  [SM0402_C]  61.34 69.22 0 top
CA74  0.1U/50V/X7R-C2  [SM0402_C]  99.31 65.91 0 top
CA75  0.1U/50V/X7R-C2  [SM0402_C]  99.31 64.9 0 top
CA76  0.1U/50V/X7R-C2  [SM0402_C]  102.87 63.25 90 top
CA77  0.1U/50V/X7R-C2  [SM0402_C]  103 60.45 270 top
CA78  0.1U/50V/X7R-C2  [SM0402_C]  83.82 57.61 270 top
CA79  0.1U/50V/X7R-C2  [SM0402_C]  82.8 57.61 270 top
CA80  0.1U/50V/X7R-C2  [SM0402_C]  49.4 57.73 270 top
CA81  0.1U/50V/X7R-C2  [SM0402_C]  141.1 53.59 180 top
CA82  0.1U/50V/X7R-C2  [SM0402_C]  82.75 51.89 90 bottom
CA83  0.1U/50V/X7R-C2  [SM0402_C]  61.44 52.27 90 top
CA84  0.1U/50V/X7R-C2  [SM0402_C]  86.69 51.89 90 bottom
CA85  0.1U/50V/X7R-C2  [SM0402_C]  141.1 47.5 180 top
CA86  0.1U/50V/X7R-C2  [SM0402_C]  141.1 46.1 180 top
CA87  0.1U/50V/X7R-C2  [SM0402_C]  141.1 44.58 180 top
CA88  0.1U/50V/X7R-C2  [SM0402_C]  45.67 45.67 180 top
CA89  0.1U/50V/X7R-C2  [SM0402_C]  12.14 21.29 90 top
CA90  0.1U/50V/X7R-C2  [SM0402_C]  15.06 21.29 90 top
CA91  0.1U/50V/X7R-C2  [SM0402_C]  18.87 21.29 90 top
CA92  0.1U/50V/X7R-C2  [SM0402_C]  22.68 21.29 90 top
CA93  0.1U/50V/X7R-C2  [SM0402_C]  34.42 17.91 90 top
CA94  0.1U/50V/X7R-C2  [SM0402_C]  35.94 17.91 90 top
CA95  0.1U/50V/X7R-C2  [SM0402_C]  37.34 17.91 90 top
CA96  0.1U/50V/X7R-C2  [SM0402_C]  43.43 17.91 90 top
CA97  0.1U/50V/X7R-C2  [SM0402_C]  54.61 17.91 90 top
CA98  0.1U/50V/X7R-C2  [SM0402_C]  56.13 17.91 90 top
CA99  0.1U/50V/X7R-C2  [SM0402_C]  57.53 17.91 90 top
CA100  0.1U/50V/X7R-C2  [SM0402_C]  63.63 17.91 90 top
CA101  0.1U/50V/X7R-C2  [SM0402_C]  74.8 17.91 90 top
CA102  0.1U/50V/X7R-C2  [SM0402_C]  76.33 17.91 90 top
CA103  0.1U/50V/X7R-C2  [SM0402_C]  77.72 17.91 90 top
CA104  0.1U/50V/X7R-C2  [SM0402_C]  83.82 17.91 90 top
CA105  0.1U/50V/X7R-C2  [SM0402_C]  95 17.91 90 top
CA106  0.1U/50V/X7R-C2  [SM0402_C]  96.52 17.91 90 top
CA107  0.1U/50V/X7R-C2  [SM0402_C]  97.92 17.91 90 top
CA108  0.1U/50V/X7R-C2  [SM0402_C]  104.01 17.91 90 top
CA109  0.1U/50V/X7R-C2  [SM0402_C]  115.19 17.91 90 top
CA110  0.1U/50V/X7R-C2  [SM0402_C]  116.71 17.91 90 top
CA111  0.1U/50V/X7R-C2  [SM0402_C]  118.11 17.91 90 top
CA112  0.1U/50V/X7R-C2  [SM0402_C]  124.21 17.91 90 top
CA113  0.1U/50V/X7R-C2  [SM0402_C]  135.38 17.91 90 top
CA114  0.1U/50V/X7R-C2  [SM0402_C]  136.91 17.91 90 top
CA115  0.1U/50V/X7R-C2  [SM0402_C]  138.3 17.91 90 top
CA116  0.1U/50V/X7R-C2  [SM0402_C]  141.35 17.91 90 top
CA117  0.1U/50V/X7R-C2  [SM0402_C]  9.78 196.72 270 bottom
CA118  0.1U/50V/X7R-C2  [SM0402_C]  93.98 191.13 180 bottom
CA119  0.1U/50V/X7R-C2  [SM0402_C]  68.58 182.75 270 bottom
CA120  0.1U/50V/X7R-C2  [SM0402_C]  119.89 181.74 0 bottom
CA121  0.1U/50V/X7R-C2  [SM0402_C]  131.57 177.42 270 bottom
CA122  0.1U/50V/X7R-C2  [SM0402_C]  93.98 177.16 180 bottom
CA123  0.1U/50V/X7R-C2  [SM0402_C]  63.75 177.04 180 bottom
CA124  0.1U/50V/X7R-C2  [SM0402_C]  68.83 173.61 90 bottom
CA125  0.1U/50V/X7R-C2  [SM0402_C]  132.21 157.48 270 bottom
CA126  0.1U/50V/X7R-C2  [SM0402_C]  109.09 155.57 0 bottom
CA127  0.1U/50V/X7R-C2  [SM0402_C]  81.92 154.94 90 bottom
CA128  0.1U/50V/X7R-C2  [SM0402_C]  80.77 154.94 90 bottom
CA129  0.1U/50V/X7R-C2  [SM0402_C]  109.09 153.16 0 bottom
CA130  0.1U/50V/X7R-C2  [SM0402_C]  142.37 149.99 90 bottom
CA131  0.1U/50V/X7R-C2  [SM0402_C]  146.56 146.81 0 bottom
CA132  0.1U/50V/X7R-C2  [SM0402_C]  146.56 143.51 90 bottom
CA133  0.1U/50V/X7R-C2  [SM0402_C]  153.16 140.46 90 bottom
CA134  0.1U/50V/X7R-C2  [SM0402_C]  143.64 139.19 270 bottom
CA135  0.1U/50V/X7R-C2  [SM0402_C]  152.78 136.65 90 bottom
CA136  0.1U/50V/X7R-C2  [SM0402_C]  117.22 126.49 180 bottom
CA137  0.1U/50V/X7R-C2  [SM0402_C]  157.89 112.01 0 bottom
CA138  0.1U/50V/X7R-C2  [SM0402_C]  141.12 108.2 270 bottom
CA139  0.1U/50V/X7R-C2  [SM0402_C]  141.12 108.2 270 top
CA140  0.1U/50V/X7R-C2  [SM0402_C]  92.74 108.58 90 bottom
CA141  0.1U/50V/X7R-C2  [SM0402_C]  83.97 109.86 0 bottom
CA142  0.1U/50V/X7R-C2  [SM0402_C]  93.37 106.3 90 bottom
CA143  0.1U/50V/X7R-C2  [SM0402_C]  82.45 105.66 270 bottom
CA144  0.1U/50V/X7R-C2  [SM0402_C]  141.48 103.38 270 top
CA145  0.1U/50V/X7R-C2  [SM0402_C]  140.34 103.38 90 top
CA146  0.1U/50V/X7R-C2  [SM0402_C]  146.56 96.14 270 bottom
CA147  0.1U/50V/X7R-C2  [SM0402_C]  140.49 89.66 0 bottom
CA148  0.1U/50V/X7R-C2  [SM0402_C]  152.93 88.39 270 bottom
CA149  0.1U/50V/X7R-C2  [SM0402_C]  137.54 75.31 180 bottom
CA150  0.1U/50V/X7R-C2  [SM0402_C]  143.89 70.1 90 bottom
CA151  0.1U/50V/X7R-C2  [SM0402_C]  142.88 70.1 90 bottom
CA152  0.1U/50V/X7R-C2  [SM0402_C]  137.03 63.75 180 bottom
CA153  0.1U/50V/X7R-C2  [SM0402_C]  152.86 20.52 270 bottom
CA246  0.1U/10V/X5R-C1  [SM0201_C]  157.35 184.15 180 bottom
CA247  0.1U/10V/X5R-C1  [SM0201_C]  157.35 184.78 180 bottom
CA248  1U/10V/X7R-C2  [SM0402_C]  17.98 80.47 90 top
CAMMH1  STANDOFF-M2.5X1.5  [HOLEC236D158-PT]  72.76 164.19 180 bottom
CAMMH2  STANDOFF-M2.5X1.5  [HOLEC236D158-PT]  106.26 196.39 180 bottom
CAMMH3  STANDOFF-M2.5X1.5  [HOLEC236D158-PT]  139.77 164.19 180 bottom
CB1  1U/6.3V/X5R-C1  [SM0201_C]  109.73 88.14 270 bottom
CB2  0.1U/6.3V/X5R-C1  [SM0201_C]  106.93 139.7 270 top
CB3  0.1U/6.3V/X5R-C1  [SM0201_C]  49.35 109.3 270 top
CB4  0.1U/6.3V/X5R-C1  [SM0201_C]  51.59 109.25 270 top
CB5  4.7U/10V/X5R-C2  [SM0402_CM]  89.79 156.84 0 top
CB6  10U/6.3V/X5R-C2  [SM0402_CM]  41.61 100.28 0 bottom
CB7  10U/6.3V/X5R-C2  [SM0402_CM]  58.88 72.72 270 top
CB8  10U/6.3V/X5R-C2  [SM0402_CM]  41.61 90.63 0 bottom
CB9  10U/6.3V/X5R-C2  [SM0402_CM]  46.81 73.3 0 top
CB10  0.1U/6.3V/X5R-C1  [SM0201_C]  91.34 101.09 180 top
CB11  0.1U/6.3V/X5R-C1  [SM0201_C]  96.82 96.93 180 top
CB12  0.1U/6.3V/X5R-C1  [SM0201_C]  112.01 96.14 0 top
CB13  0.1U/6.3V/X5R-C1  [SM0201_C]  112.04 95.38 0 top
CB14  0.1U/6.3V/X5R-C1  [SM0201_C]  133.22 93.34 270 top
CB15  0.1U/6.3V/X5R-C1  [SM0201_C]  51.16 91.39 180 top
CB16  0.1U/6.3V/X5R-C1  [SM0201_C]  57.57 91.39 0 top
CB17  0.1U/6.3V/X5R-C1  [SM0201_C]  67.94 89.83 90 top
CB18  0.1U/6.3V/X5R-C1  [SM0201_C]  68.73 89.83 90 top
CB19  0.1U/6.3V/X5R-C1  [SM0201_C]  113.18 89.03 180 top
CB20  0.1U/6.3V/X5R-C1  [SM0201_C]  101.63 81.28 90 top
CB21  0.1U/6.3V/X5R-C1  [SM0201_C]  91.69 76.58 90 top
CB22  0.1U/6.3V/X5R-C1  [SM0201_C]  92.33 76.58 90 top
CB23  0.1U/6.3V/X5R-C1  [SM0201_C]  93.98 76.58 90 top
CB24  0.1U/6.3V/X5R-C1  [SM0201_C]  94.61 76.58 90 top
CB25  0.1U/6.3V/X5R-C1  [SM0201_C]  96.27 76.58 90 top
CB26  0.1U/6.3V/X5R-C1  [SM0201_C]  96.9 76.58 90 top
CB27  0.1U/6.3V/X5R-C1  [SM0201_C]  98.55 76.58 90 top
CB28  0.1U/6.3V/X5R-C1  [SM0201_C]  99.19 76.58 90 top
CB29  0.1U/6.3V/X5R-C1  [SM0201_C]  63.83 75.39 180 top
CB30  0.1U/6.3V/X5R-C1  [SM0201_C]  133.35 53.34 270 top
CB31  0.1U/6.3V/X5R-C1  [SM0201_C]  134.11 53.34 270 top
CB32  0.1U/6.3V/X5R-C1  [SM0201_C]  131.83 53.21 270 top
CB33  0.1U/6.3V/X5R-C1  [SM0201_C]  126.87 53.09 0 top
CB34  0.1U/6.3V/X5R-C1  [SM0201_C]  126.87 52.32 0 top
CB35  0.1U/6.3V/X5R-C1  [SM0201_C]  134.99 50.29 180 top
CB36  0.1U/6.3V/X5R-C1  [SM0201_C]  126.89 49.78 0 top
CB37  0.1U/6.3V/X5R-C1  [SM0201_C]  135.13 49.15 180 top
CB38  0.1U/6.3V/X5R-C1  [SM0201_C]  135.13 48.51 180 top
CB39  0.1U/6.3V/X5R-C1  [SM0201_C]  135.12 47.62 180 top
CB40  0.1U/6.3V/X5R-C1  [SM0201_C]  135.51 44.7 180 top
CB41  0.1U/6.3V/X5R-C1  [SM0201_C]  130.68 44.34 90 top
CB42  0.1U/6.3V/X5R-C1  [SM0201_C]  129.67 44.32 90 top
CB43  0.1U/6.3V/X5R-C1  [SM0201_C]  28.07 37.21 270 top
CB44  0.1U/6.3V/X5R-C1  [SM0201_C]  28.83 37.21 270 top
CB45  0.1U/6.3V/X5R-C1  [SM0201_C]  25.17 37.21 270 top
CB46  0.1U/6.3V/X5R-C1  [SM0201_C]  136.27 34.59 270 top
CB47  0.1U/6.3V/X5R-C1  [SM0201_C]  137.03 34.59 270 top
CB48  0.1U/6.3V/X5R-C1  [SM0201_C]  133.86 34.54 270 top
CB49  0.1U/6.3V/X5R-C1  [SM0201_C]  20.07 34.29 0 top
CB50  0.1U/6.3V/X5R-C1  [SM0201_C]  44.83 34.21 270 top
CB51  0.1U/6.3V/X5R-C1  [SM0201_C]  45.59 34.21 270 top
CB52  0.1U/6.3V/X5R-C1  [SM0201_C]  63.12 34.21 270 top
CB53  0.1U/6.3V/X5R-C1  [SM0201_C]  63.88 34.21 270 top
CB54  0.1U/6.3V/X5R-C1  [SM0201_C]  81.41 34.21 270 top
CB55  0.1U/6.3V/X5R-C1  [SM0201_C]  82.17 34.21 270 top
CB56  0.1U/6.3V/X5R-C1  [SM0201_C]  99.69 34.21 270 top
CB57  0.1U/6.3V/X5R-C1  [SM0201_C]  100.46 34.21 270 top
CB58  0.1U/6.3V/X5R-C1  [SM0201_C]  117.98 34.21 270 top
CB59  0.1U/6.3V/X5R-C1  [SM0201_C]  118.75 34.21 270 top
CB60  0.1U/6.3V/X5R-C1  [SM0201_C]  42.42 34.16 270 top
CB61  0.1U/6.3V/X5R-C1  [SM0201_C]  60.71 34.16 270 top
CB62  0.1U/6.3V/X5R-C1  [SM0201_C]  78.99 34.16 270 top
CB63  0.1U/6.3V/X5R-C1  [SM0201_C]  97.28 34.16 270 top
CB64  0.1U/6.3V/X5R-C1  [SM0201_C]  115.57 34.16 270 top
CB65  0.1U/6.3V/X5R-C1  [SM0201_C]  20.07 33.6 0 top
CB66  0.1U/6.3V/X5R-C1  [SM0201_C]  28.96 32.13 180 top
CB67  0.1U/6.3V/X5R-C1  [SM0201_C]  128.27 31.75 0 top
CB68  0.1U/6.3V/X5R-C1  [SM0201_C]  36.83 31.37 0 top
CB69  0.1U/6.3V/X5R-C1  [SM0201_C]  55.12 31.37 0 top
CB70  0.1U/6.3V/X5R-C1  [SM0201_C]  73.41 31.37 0 top
CB71  0.1U/6.3V/X5R-C1  [SM0201_C]  91.69 31.37 0 top
CB72  0.1U/6.3V/X5R-C1  [SM0201_C]  109.98 31.37 0 top
CB73  0.1U/6.3V/X5R-C1  [SM0201_C]  128.27 30.99 0 top
CB74  0.1U/6.3V/X5R-C1  [SM0201_C]  36.83 30.61 0 top
CB75  0.1U/6.3V/X5R-C1  [SM0201_C]  55.12 30.61 0 top
CB76  0.1U/6.3V/X5R-C1  [SM0201_C]  73.41 30.61 0 top
CB77  0.1U/6.3V/X5R-C1  [SM0201_C]  91.69 30.61 0 top
CB78  0.1U/6.3V/X5R-C1  [SM0201_C]  109.98 30.61 0 top
CB79  0.1U/6.3V/X5R-C1  [SM0201_C]  29.02 30.56 180 top
CB80  0.1U/6.3V/X5R-C1  [SM0201_C]  29.02 29.79 180 top
CB81  0.1U/6.3V/X5R-C1  [SM0201_C]  137.16 29.59 180 top
CB82  0.1U/6.3V/X5R-C1  [SM0201_C]  45.72 29.21 180 top
CB83  0.1U/6.3V/X5R-C1  [SM0201_C]  64.01 29.21 180 top
CB84  0.1U/6.3V/X5R-C1  [SM0201_C]  82.3 29.21 180 top
CB85  0.1U/6.3V/X5R-C1  [SM0201_C]  100.58 29.21 180 top
CB86  0.1U/6.3V/X5R-C1  [SM0201_C]  118.87 29.21 180 top
CB87  0.1U/6.3V/X5R-C1  [SM0201_C]  28.02 28.92 90 top
CB88  0.1U/6.3V/X5R-C1  [SM0201_C]  24.31 28.8 90 top
CB89  0.1U/6.3V/X5R-C1  [SM0201_C]  25.07 28.8 90 top
CB90  0.1U/6.3V/X5R-C1  [SM0201_C]  23.42 28.79 90 top
CB91  0.1U/6.3V/X5R-C1  [SM0201_C]  20.85 28.49 90 top
CB92  0.1U/6.3V/X5R-C1  [SM0201_C]  137.16 27.99 180 top
CB93  0.1U/6.3V/X5R-C1  [SM0201_C]  45.72 27.61 180 top
CB94  0.1U/6.3V/X5R-C1  [SM0201_C]  64.01 27.61 180 top
CB95  0.1U/6.3V/X5R-C1  [SM0201_C]  82.3 27.61 180 top
CB96  0.1U/6.3V/X5R-C1  [SM0201_C]  100.58 27.61 180 top
CB97  0.1U/6.3V/X5R-C1  [SM0201_C]  118.87 27.61 180 top
CB98  0.1U/6.3V/X5R-C1  [SM0201_C]  137.16 27.23 180 top
CB99  0.1U/6.3V/X5R-C1  [SM0201_C]  45.72 26.85 180 top
CB100  0.1U/6.3V/X5R-C1  [SM0201_C]  64.01 26.85 180 top
CB101  0.1U/6.3V/X5R-C1  [SM0201_C]  82.3 26.85 180 top
CB102  0.1U/6.3V/X5R-C1  [SM0201_C]  100.58 26.85 180 top
CB103  0.1U/6.3V/X5R-C1  [SM0201_C]  118.87 26.85 180 top
CB104  0.1U/6.3V/X5R-C1  [SM0201_C]  131.57 26.26 90 top
CB105  0.1U/6.3V/X5R-C1  [SM0201_C]  132.54 26.26 90 top
CB106  0.1U/6.3V/X5R-C1  [SM0201_C]  133.3 26.26 90 top
CB107  0.1U/6.3V/X5R-C1  [SM0201_C]  134.19 26.26 90 top
CB108  0.1U/6.3V/X5R-C1  [SM0201_C]  128.65 25.91 90 top
CB109  0.1U/6.3V/X5R-C1  [SM0201_C]  40.13 25.88 90 top
CB110  0.1U/6.3V/X5R-C1  [SM0201_C]  41.1 25.88 90 top
CB111  0.1U/6.3V/X5R-C1  [SM0201_C]  41.86 25.88 90 top
CB112  0.1U/6.3V/X5R-C1  [SM0201_C]  42.75 25.88 90 top
CB113  0.1U/6.3V/X5R-C1  [SM0201_C]  58.42 25.88 90 top
CB114  0.1U/6.3V/X5R-C1  [SM0201_C]  59.39 25.88 90 top
CB115  0.1U/6.3V/X5R-C1  [SM0201_C]  60.15 25.88 90 top
CB116  0.1U/6.3V/X5R-C1  [SM0201_C]  61.04 25.88 90 top
CB117  0.1U/6.3V/X5R-C1  [SM0201_C]  76.71 25.88 90 top
CB118  0.1U/6.3V/X5R-C1  [SM0201_C]  77.67 25.88 90 top
CB119  0.1U/6.3V/X5R-C1  [SM0201_C]  78.44 25.88 90 top
CB120  0.1U/6.3V/X5R-C1  [SM0201_C]  79.32 25.88 90 top
CB121  0.1U/6.3V/X5R-C1  [SM0201_C]  95 25.88 90 top
CB122  0.1U/6.3V/X5R-C1  [SM0201_C]  95.96 25.88 90 top
CB123  0.1U/6.3V/X5R-C1  [SM0201_C]  96.72 25.88 90 top
CB124  0.1U/6.3V/X5R-C1  [SM0201_C]  97.61 25.88 90 top
CB125  0.1U/6.3V/X5R-C1  [SM0201_C]  113.28 25.88 90 top
CB126  0.1U/6.3V/X5R-C1  [SM0201_C]  114.25 25.88 90 top
CB127  0.1U/6.3V/X5R-C1  [SM0201_C]  115.01 25.88 90 top
CB128  0.1U/6.3V/X5R-C1  [SM0201_C]  115.9 25.88 90 top
CB129  0.1U/6.3V/X5R-C1  [SM0201_C]  37.21 25.53 90 top
CB130  0.1U/6.3V/X5R-C1  [SM0201_C]  55.5 25.53 90 top
CB131  0.1U/6.3V/X5R-C1  [SM0201_C]  73.79 25.53 90 top
CB132  0.1U/6.3V/X5R-C1  [SM0201_C]  92.08 25.53 90 top
CB133  0.1U/6.3V/X5R-C1  [SM0201_C]  110.36 25.53 90 top
CB134  0.1U/6.3V/X5R-C1  [SM0201_C]  138.68 177.32 180 bottom
CB135  0.1U/6.3V/X5R-C1  [SM0201_C]  127.89 143.23 90 bottom
CB136  0.1U/6.3V/X5R-C1  [SM0201_C]  143.89 93.22 270 bottom
CB137  0.1U/6.3V/X5R-C1  [SM0201_C]  108.97 88.14 270 bottom
CB138  0.1U/6.3V/X5R-C1  [SM0201_C]  111.66 83.31 180 bottom
CB139  0.1U/6.3V/X5R-C1  [SM0201_C]  131.32 55.12 90 bottom
CB140  0.1U/6.3V/X5R-C1  [SM0201_C]  127.25 42.16 180 bottom
CB141  0.1U/6.3V/X5R-C1  [SM0201_C]  17.91 36.7 90 bottom
